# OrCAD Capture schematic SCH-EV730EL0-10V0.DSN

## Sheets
1 USB&POWER: size C; title: EV730EL0_USB&POWER; rev: 1.3; note: Ver1.0
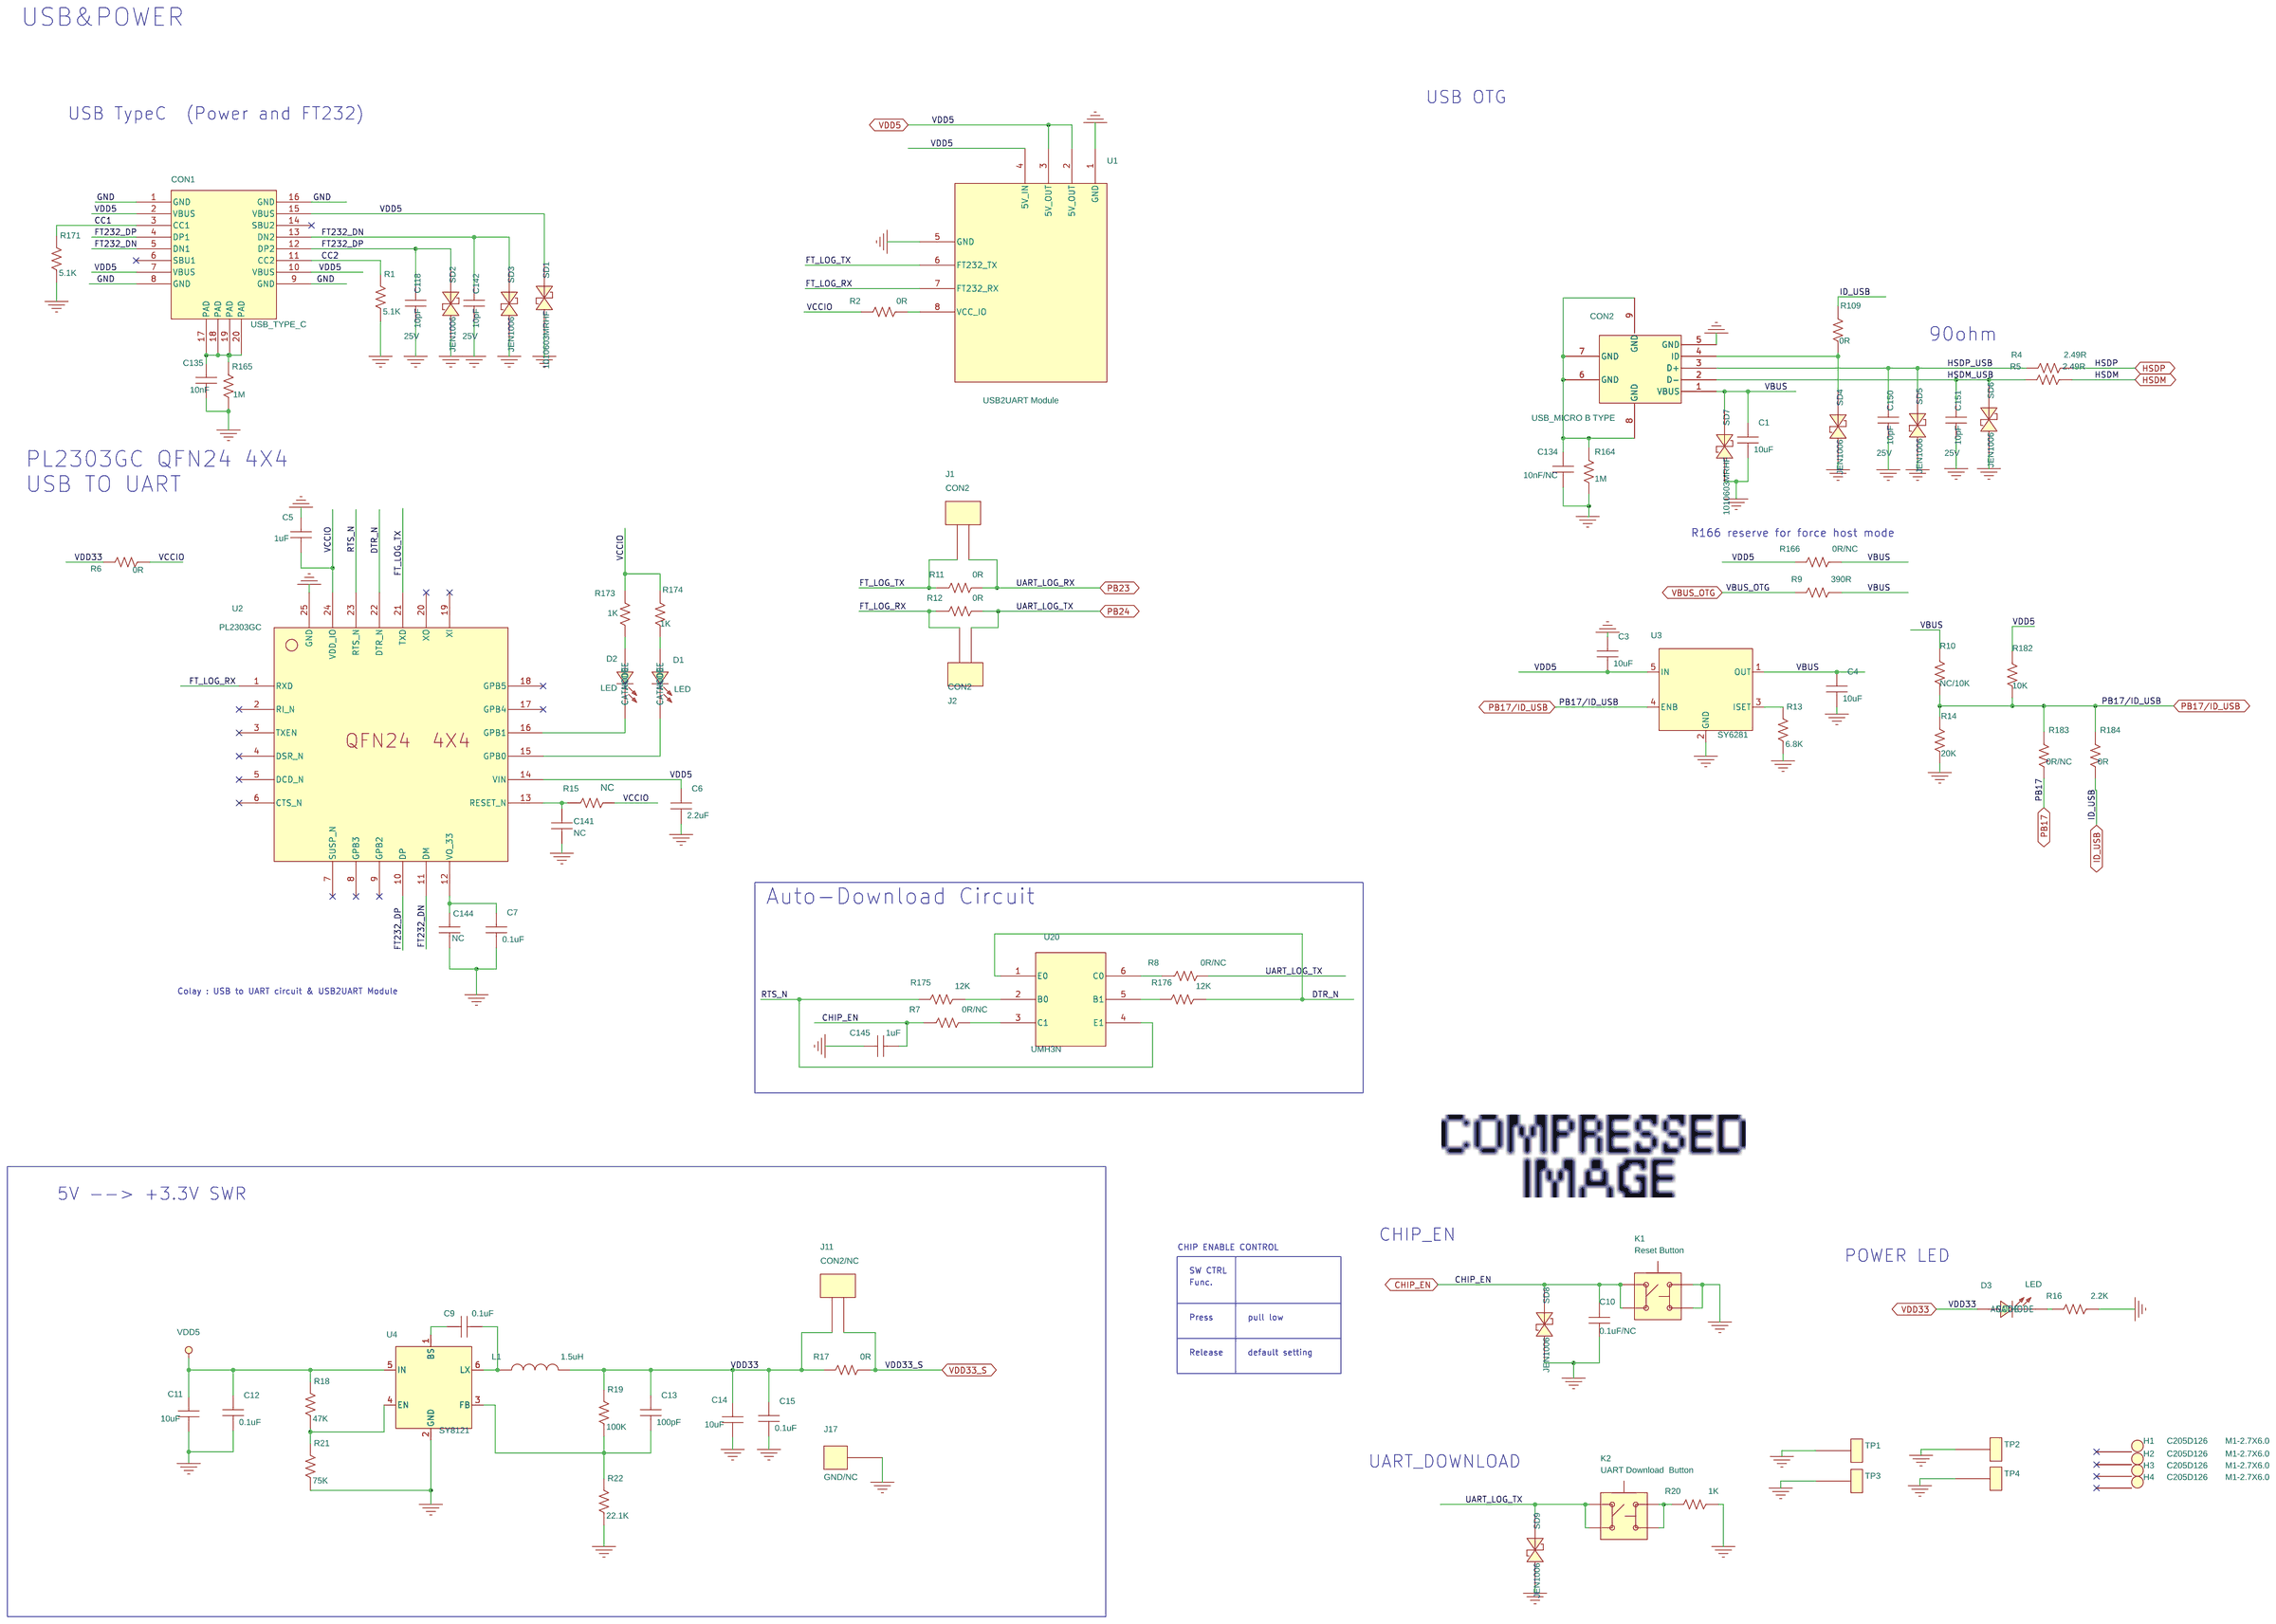
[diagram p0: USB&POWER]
2 8730EL_QFN144: size A2; title: EV730EL0
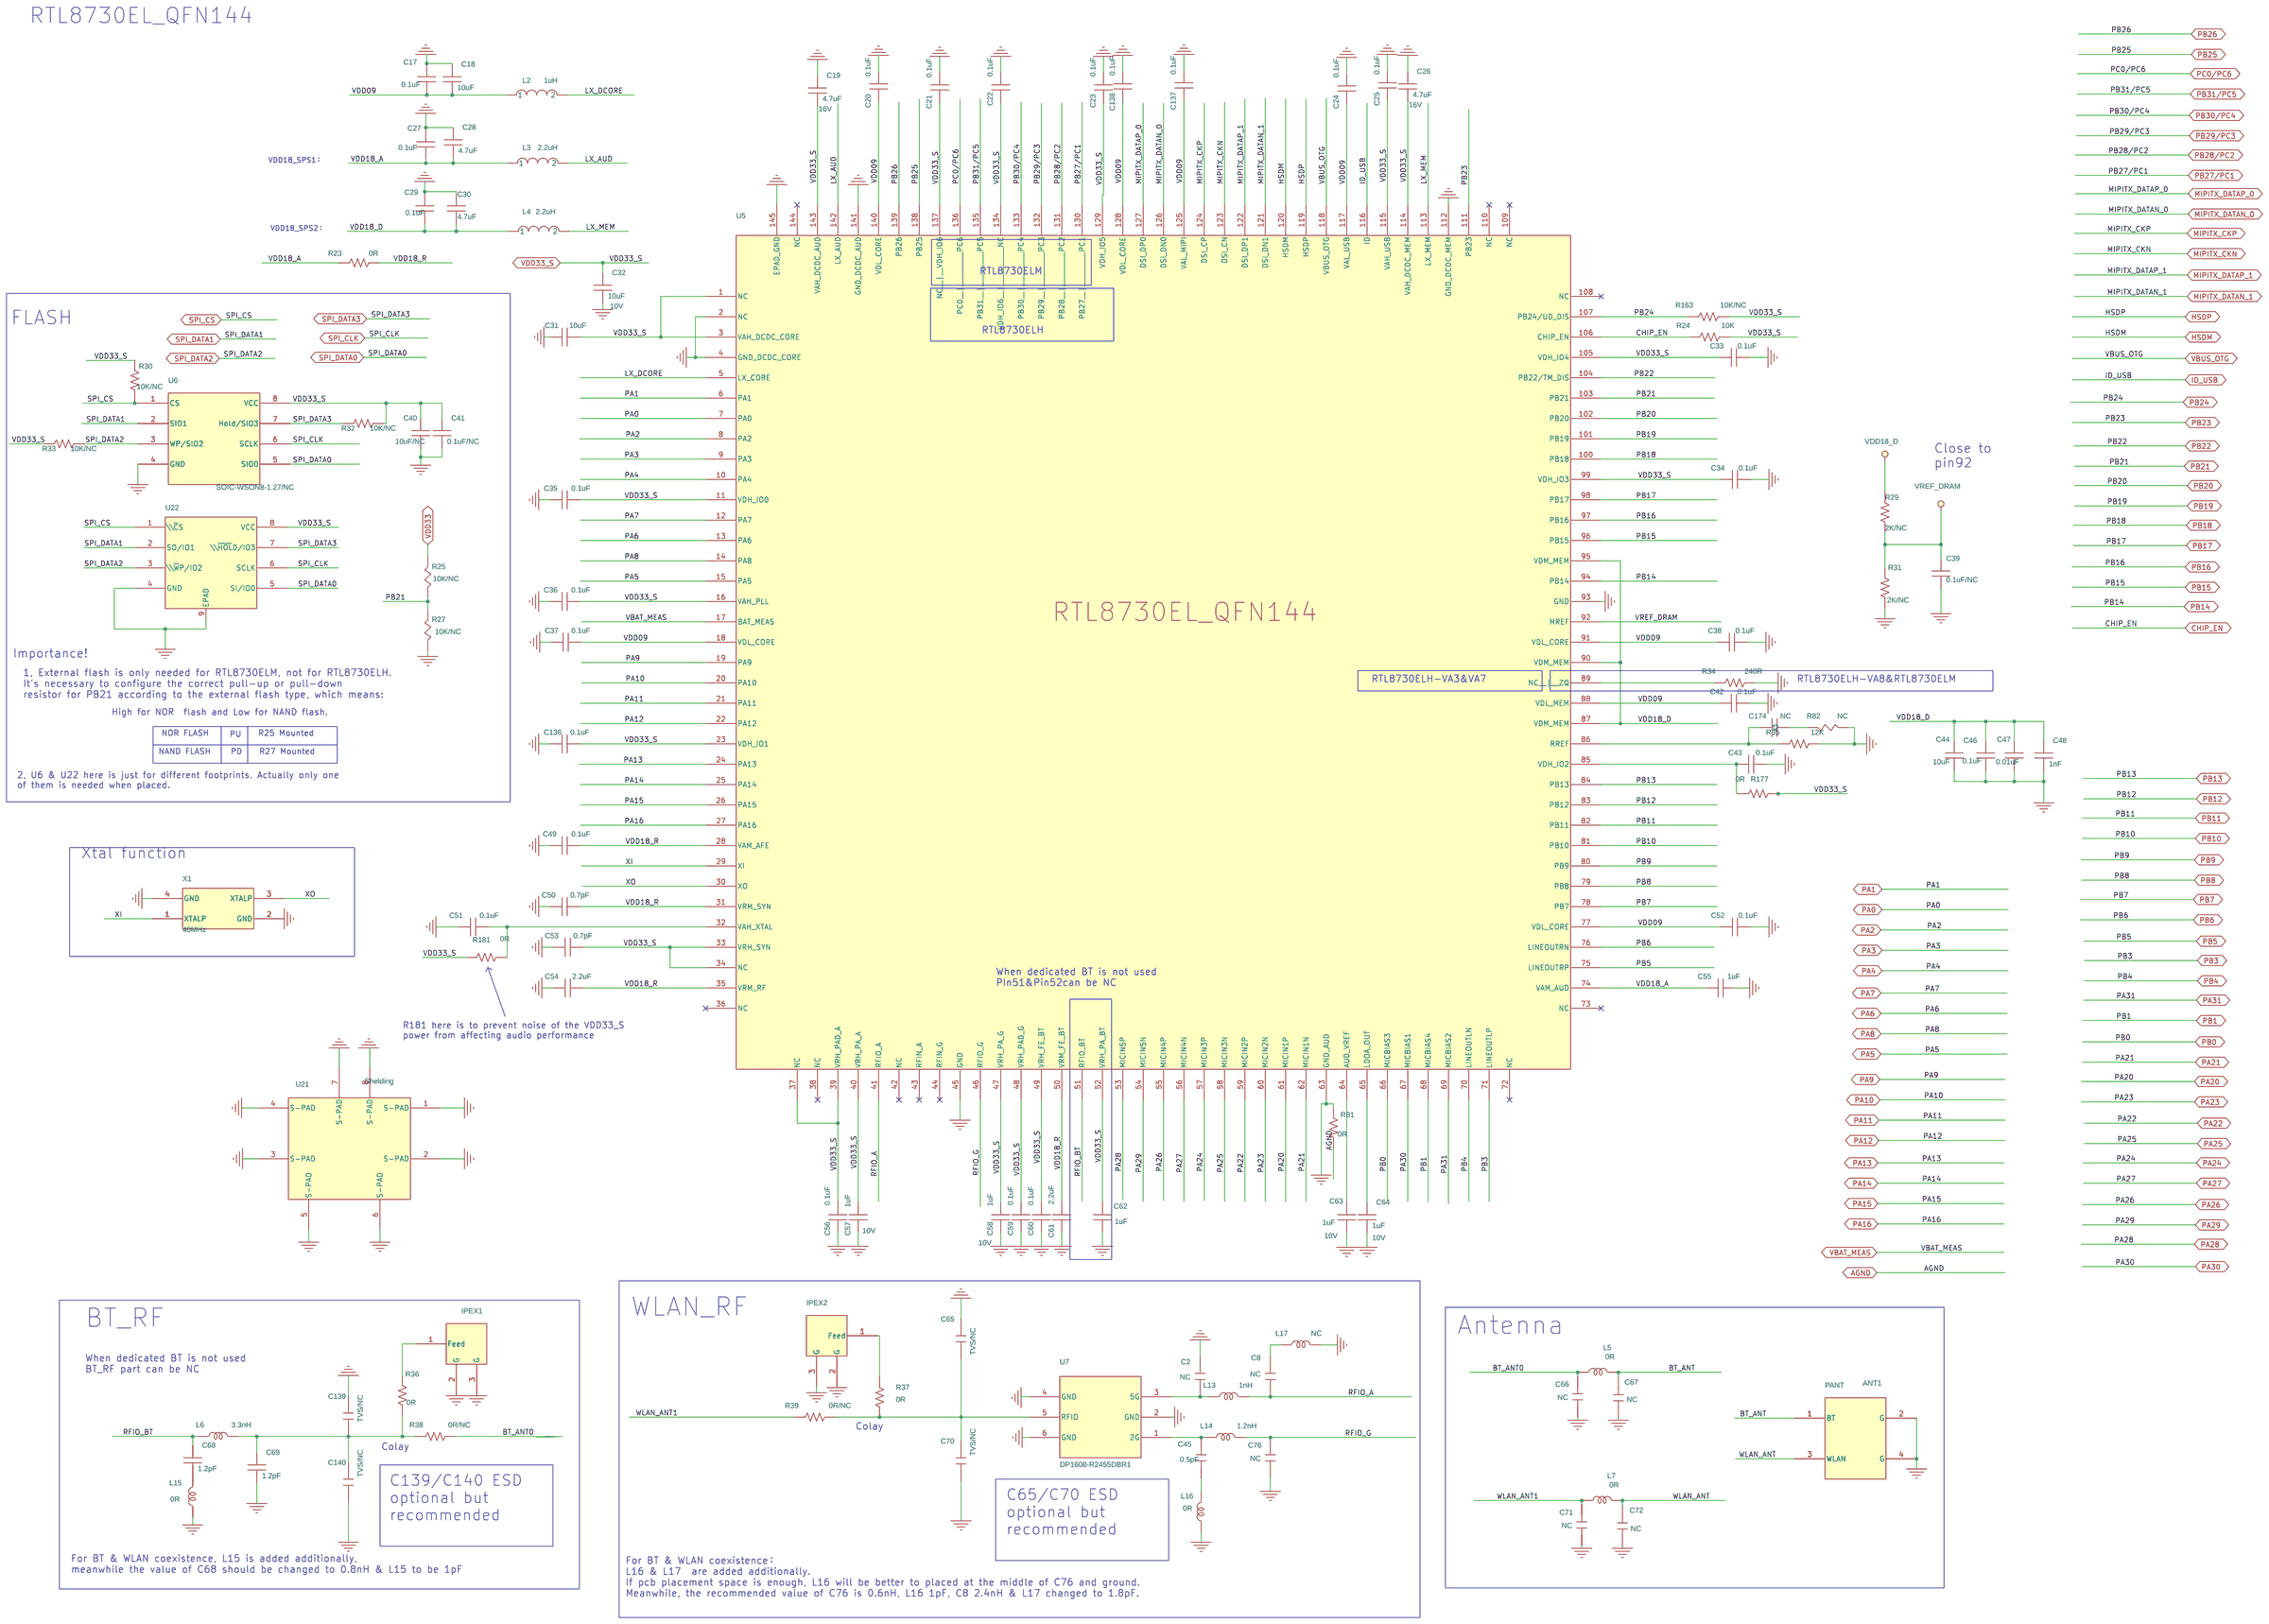
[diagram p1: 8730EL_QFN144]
3 AUDIO: size C; title: EV730EL0_AUDIO
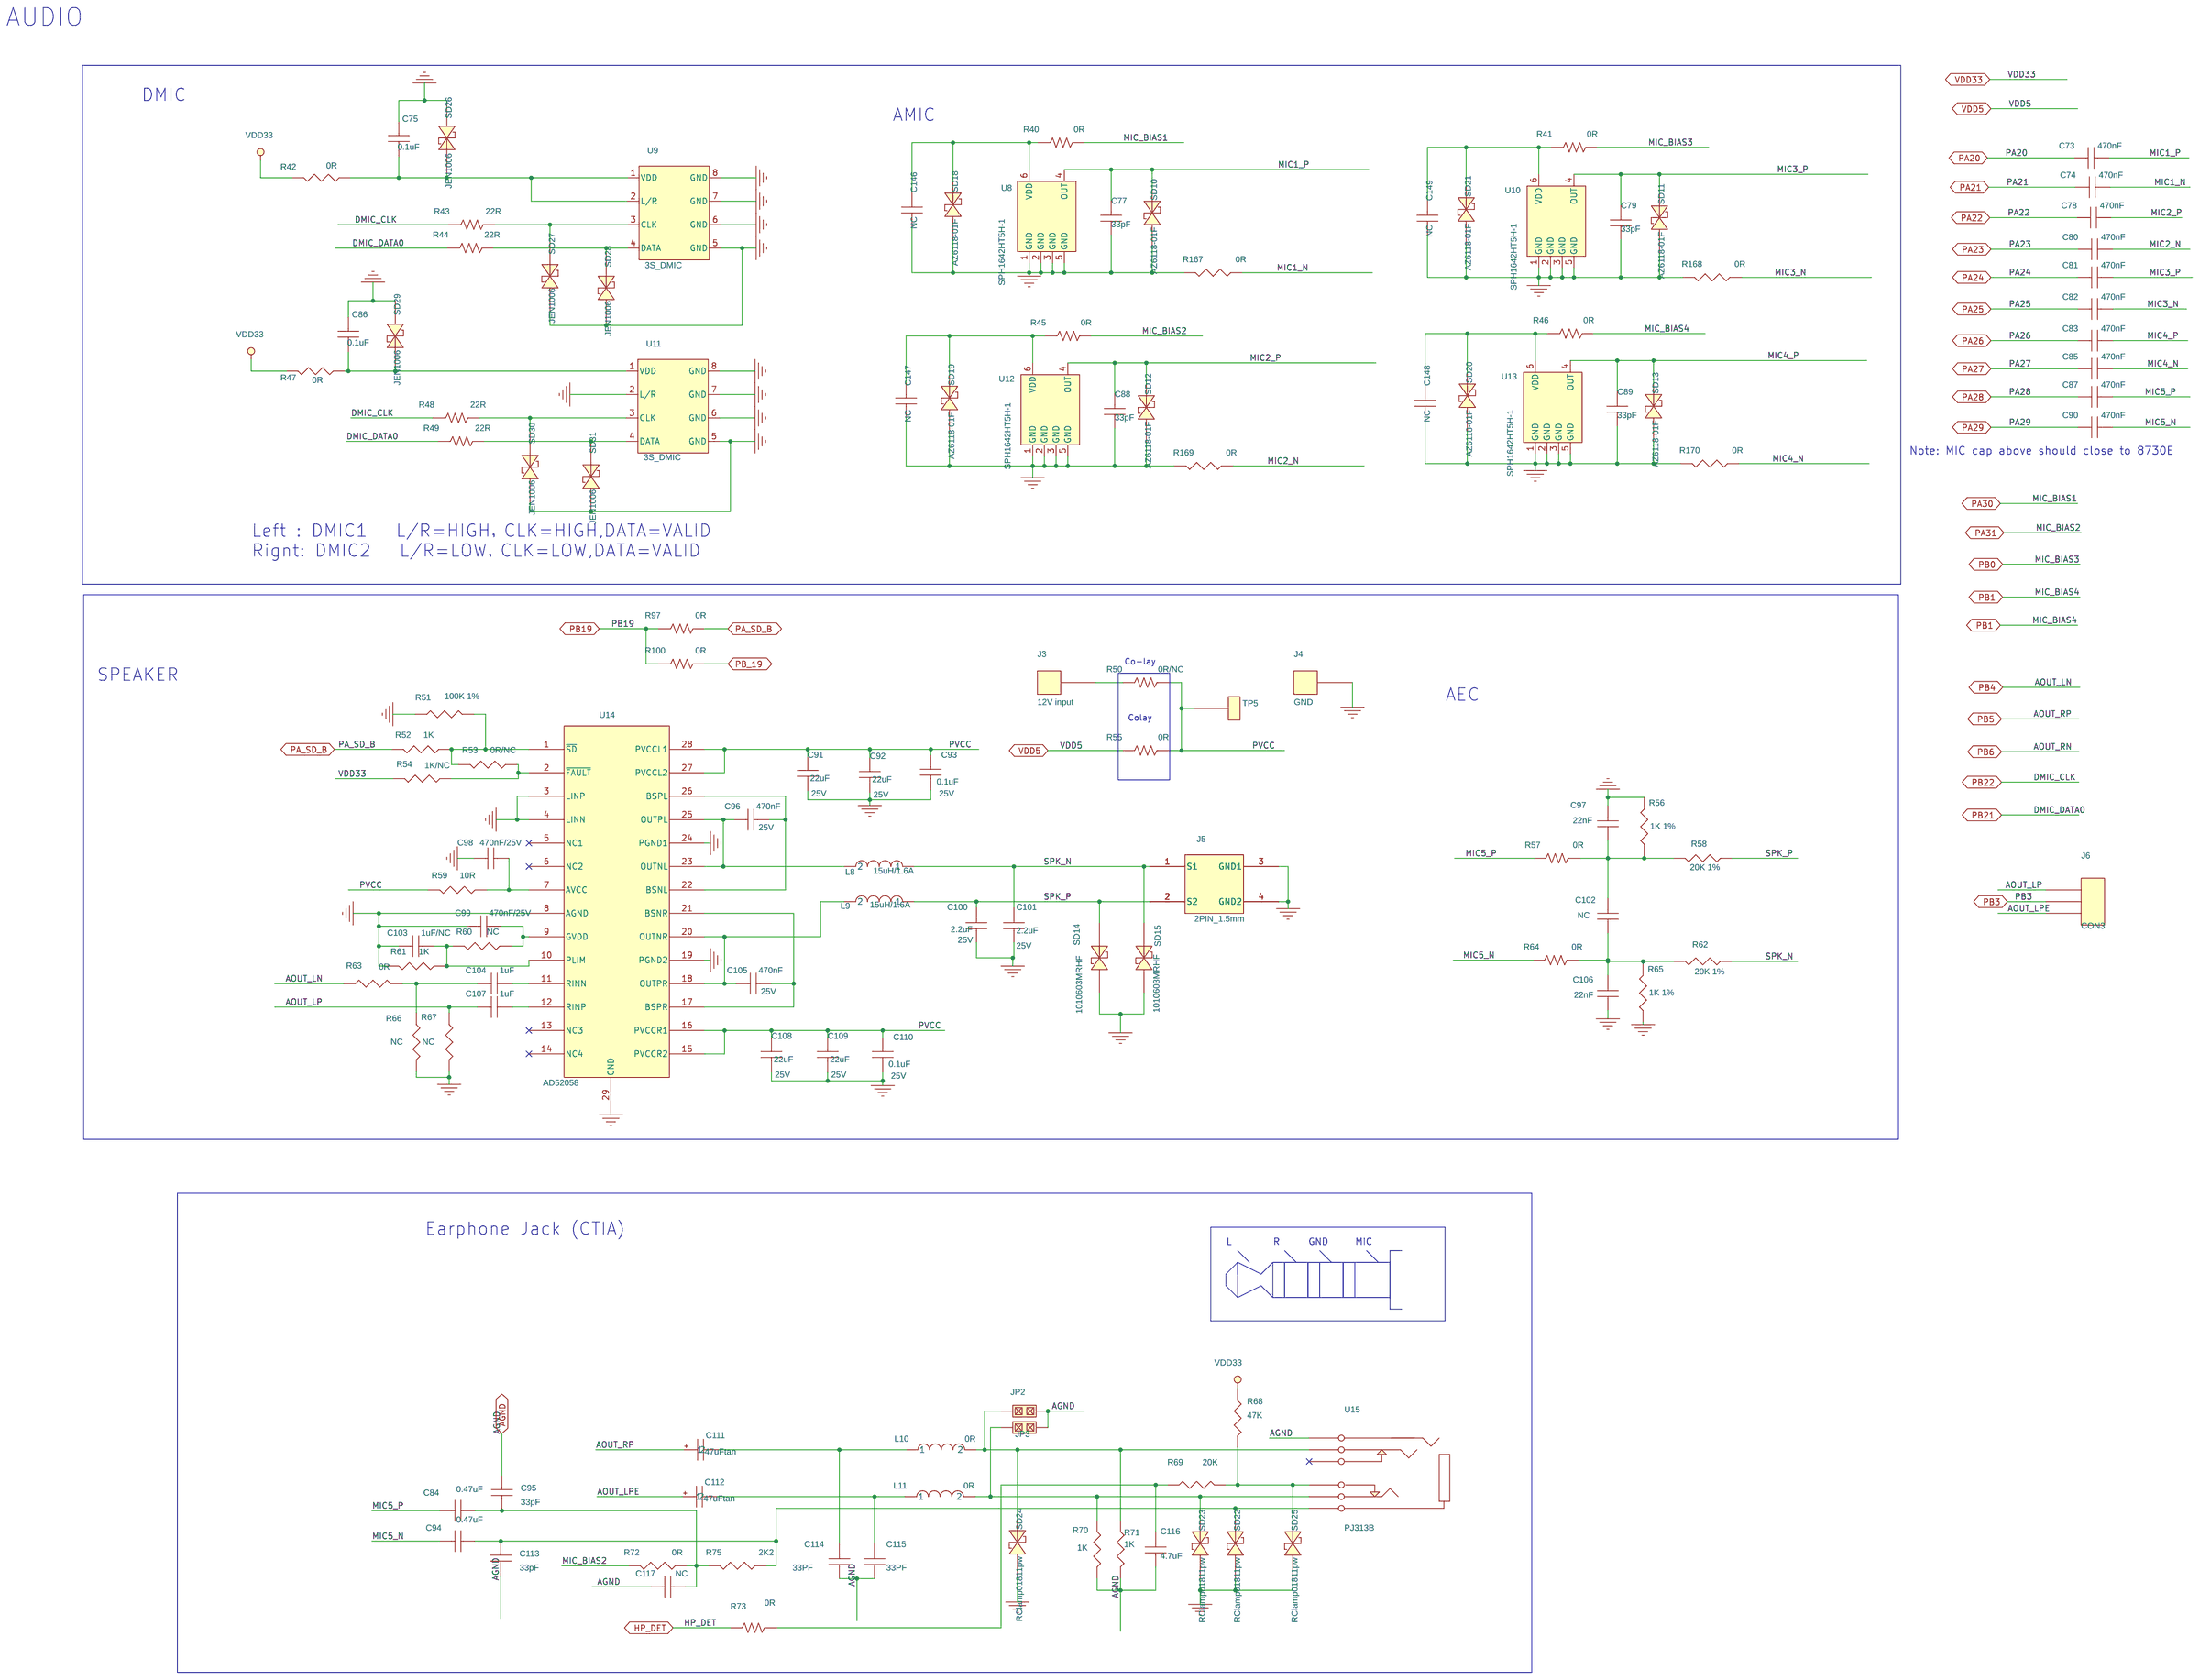
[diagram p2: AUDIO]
4 Peripheral: size C; title: EV730EL0_Peripheral
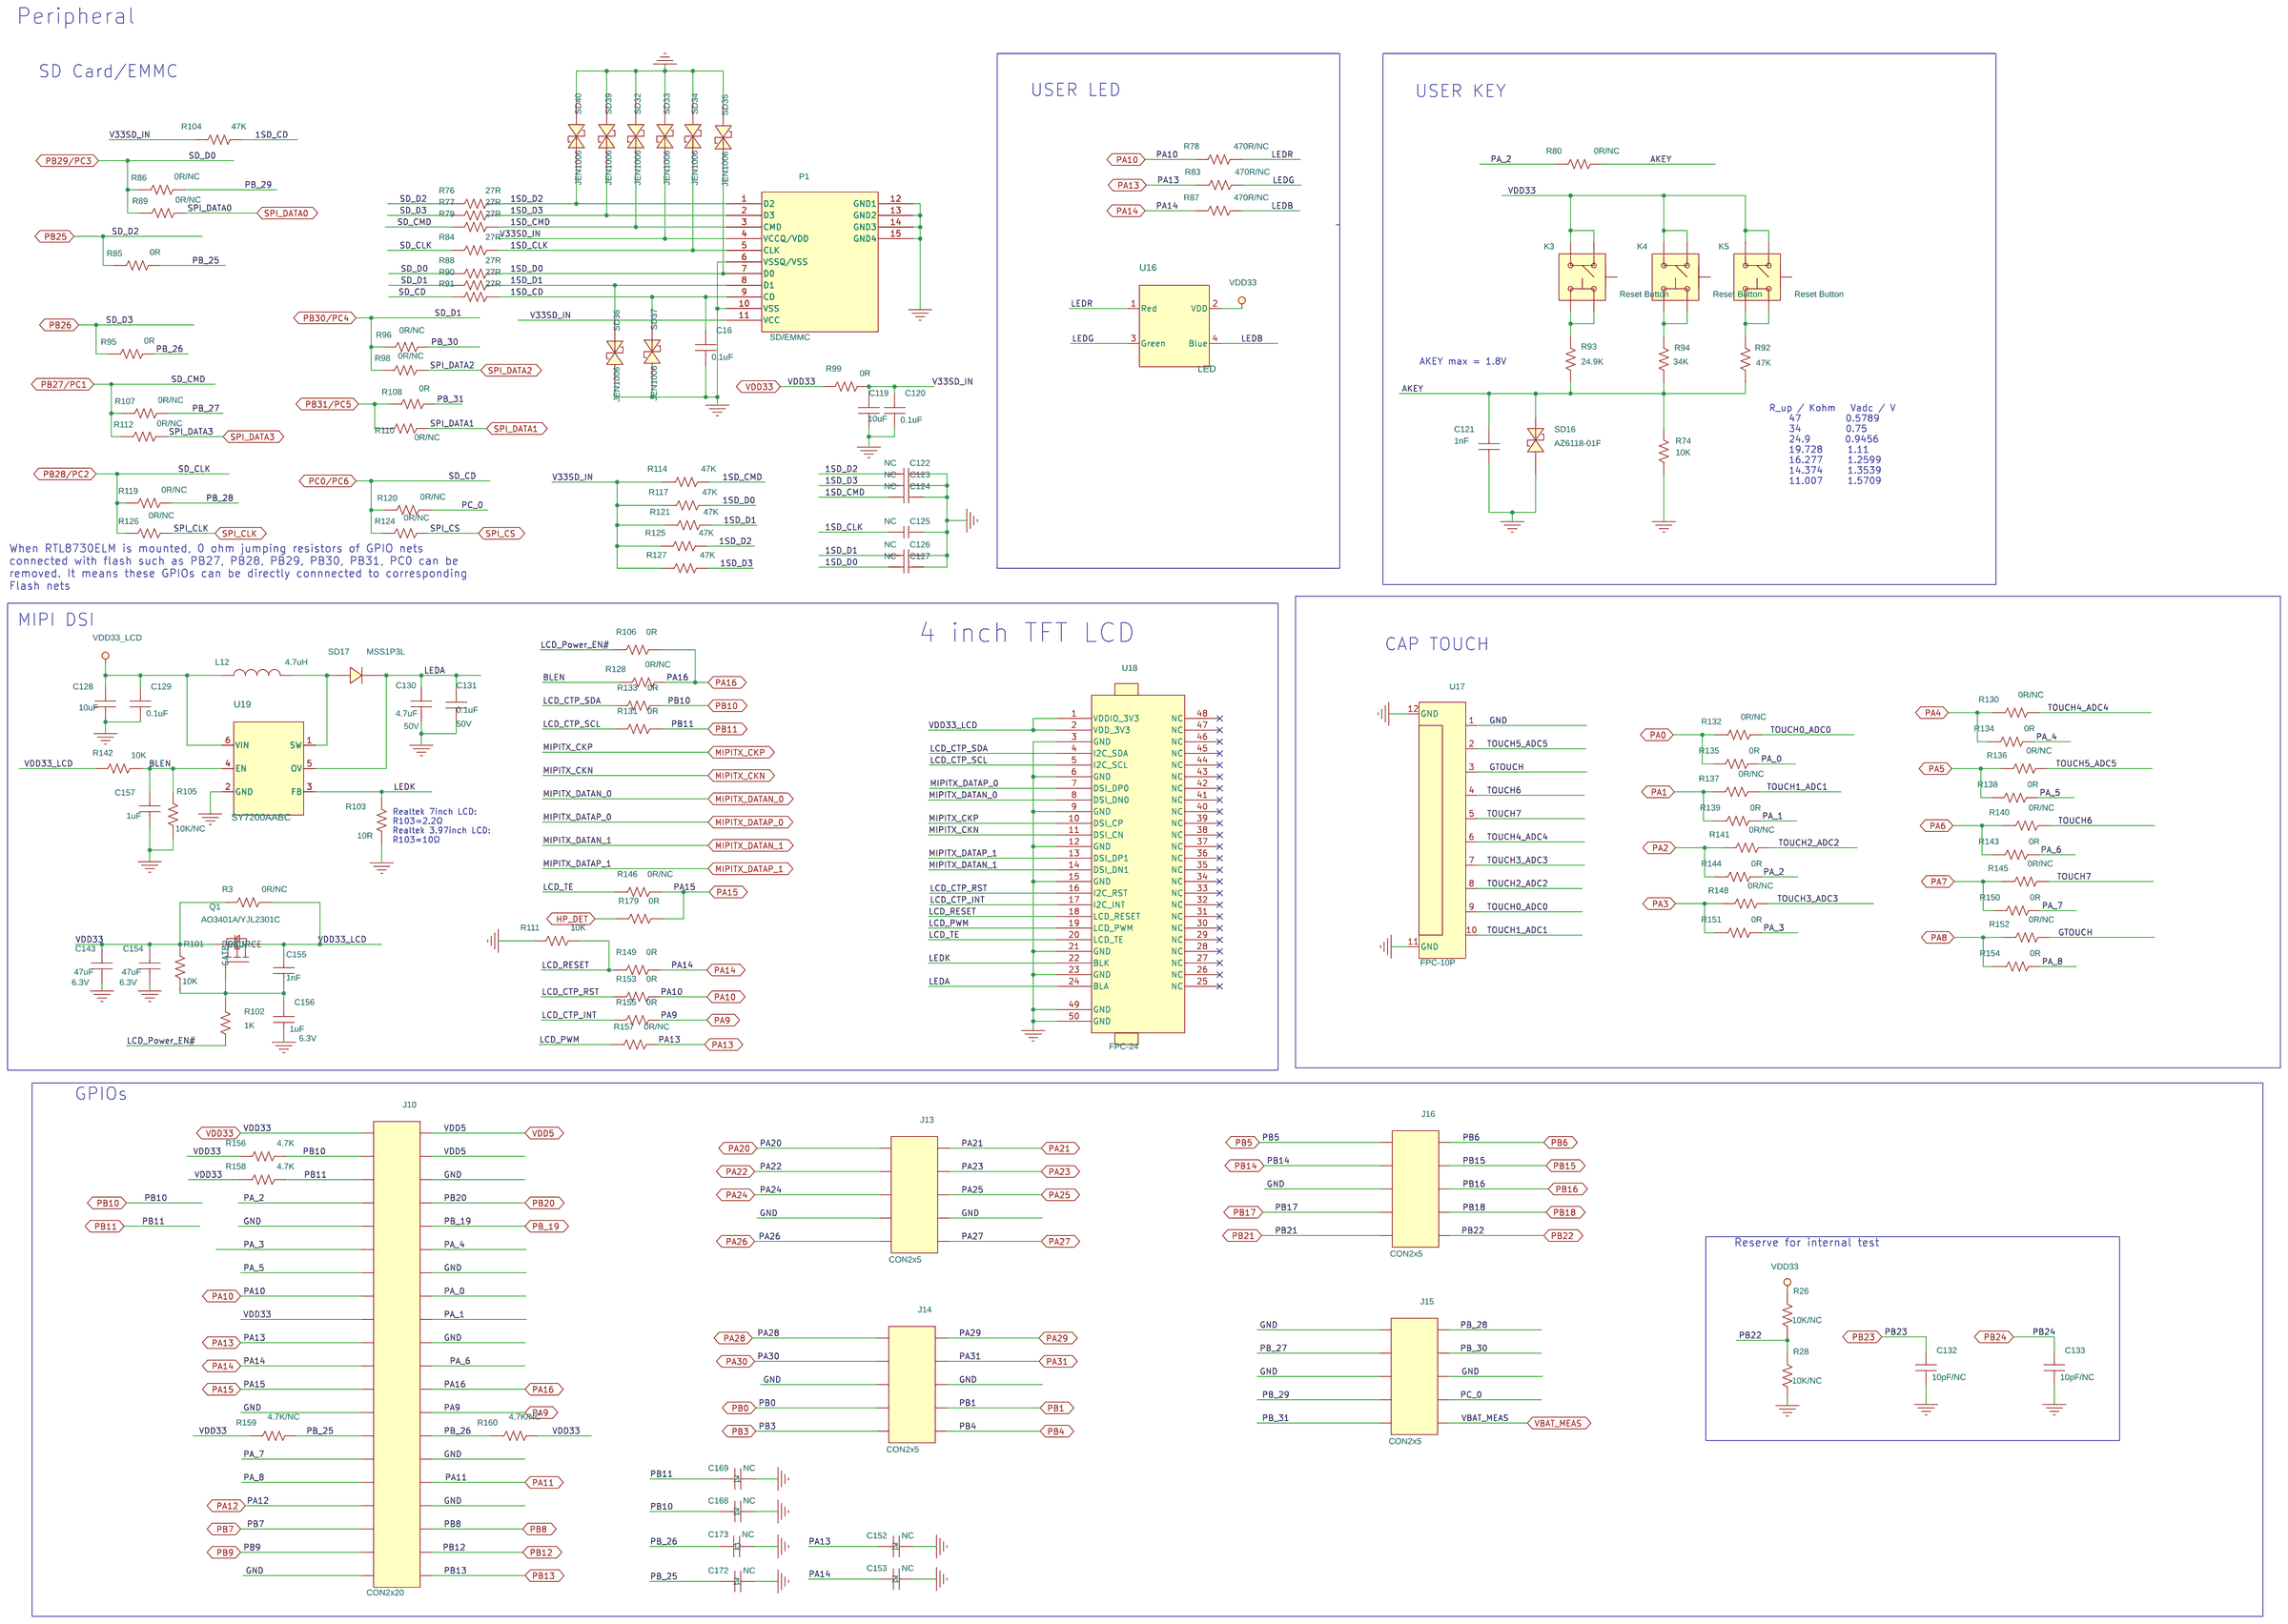
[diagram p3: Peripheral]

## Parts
sheet 8730EL_QFN144
ANT1  PANT  [8730EL_EVB_ANT]
C2  NC  [C0201]
C8  NC  [C0201]
C17  0.1uF  [C0201]
C18  10uF  [C0402]
C19  4.7uF  [C0402]
C20  0.1uF  [C0201]
C21  0.1uF  [C0201]
C22  0.1uF  [C0201]
C23  0.1uF  [C0201]
C24  0.1uF  [C0201]
C25  0.1uF  [C0201]
C26  4.7uF  [C0402]
C27  0.1uF  [C0201]
C28  4.7uF  [C0402]
C29  0.1uF  [C0201]
C30  4.7uF  [C0402]
C31  10uF  [C0402]
C32  10uF  [C0402]
C33  0.1uF  [C0201]
C34  0.1uF  [C0201]
C35  0.1uF  [C0201]
C36  0.1uF  [C0201]
C37  0.1uF  [C0201]
C38  0.1uF  [C0201]
C39  0.1uF/NC  [C0201]
C40  10uF/NC  [C0402]
C41  0.1uF/NC  [C0201]
C42  0.1uF  [C0201]
C43  0.1uF  [C0402]
C44  10uF  [C0402]
C45  0.5pF  [C0201]
C46  0.1uF  [C0201]
C47  0.01uF  [C0201]
C48  1nF  [C0201]
C49  0.1uF  [C0201]
C50  0.7pF  [C0201]
C51  0.1uF  [C0201]
C52  0.1uF  [C0201]
C53  0.7pF  [C0201]
C54  2.2uF  [C0201]
C55  1uF  [C0201]
C56  0.1uF  [C0201]
C57  1uF  [C0201]
C58  1uF  [C0201]
C59  0.1uF  [C0201]
C60  0.1uF  [C0201]
C61  2.2uF  [C0201]
C62  1uF  [C0201]
C63  1uF  [C0201]
C64  1uF  [C0201]
C65  TVS/NC  [C0201]
C66  NC  [C0201]
C67  NC  [C0201]
C68  1.2pF  [C0201]
C69  1.2pF  [C0201]
C70  TVS/NC  [C0402]
C71  NC  [C0201]
C72  NC  [C0201]
C76  NC  [C0201]
C136  0.1uF  [C0201]
C137  0.1uF  [C0201]
C138  0.1uF  [C0201]
C139  TVS/NC  [C0201]
C140  TVS/NC  [C0402]
C174  NC  [C0201]
IPEX1  TP  [IPEX-0.7X2.2-1.35]
IPEX2  TP  [IPEX-0.7X2.2-1.35]
L2  1uH  [L2016]
L3  2.2uH  [L2016]
L4  2.2uH  [L2016]
L5  0R  [L0201]
L6  3.3nH  [L0201]
L7  0R  [L0201]
L13  1nH  [L0201]
L14  1.2nH  [L0201]
L15  0R  [L0201]
L16  0R  [L0201]
L17  NC  [L0201]
R23  0R  [R0402]
R24  10K  [R0201]
R25  10K/NC  [R0201]
R27  10K/NC  [R0201]
R29  2K/NC  [R0201]
R30  10K/NC  [R0402]
R31  2K/NC  [R0201]
R32  10K/NC  [R0402]
R33  10K/NC  [R0402]
R34  240R  [R0201]
R35  12K  [R0201]
R36  0R  [R0201]
R37  0R  [R0201]
R38  0R/NC  [R0201]
R39  0R/NC  [R0201]
R81  0R  [R0201]
R82  NC  [R0201]
R163  10K/NC  [R0201]
R177  0R  [R0201]
R181  0R  [R0201]
U5  RL8730ELH  [QFN144-11X11_SMART]
U6  SOIC-WSON8-1.27/NC  [SOIC-WSON8-1.27]
U7  DP1608-R2455DBR1  [DPX1608-6-0.55-0.3X0.4]
U21  Shelding  [Shelding-144pin]
U22  Flash_2  [WSON8-1.27-8X6]
X1  40MHz  [XTAL-2016]
sheet AUDIO
C73  470nF  [C0201]
C74  470nF  [C0201]
C75  0.1uF  [C0402]
C77  33pF  [C0402]
C78  470nF  [C0201]
C79  33pF  [C0402]
C80  470nF  [C0201]
C81  470nF  [C0201]
C82  470nF  [C0201]
C83  470nF  [C0201]
C84  0.47uF  [C0402]
C85  470nF  [C0201]
C86  0.1uF  [C0402]
C87  470nF  [C0201]
C88  33pF  [C0402]
C89  33pF  [C0402]
C90  470nF  [C0201]
C91  22uF  [C0805]
C92  22uF  [C0805]
C93  0.1uF  [C0402]
C94  0.47uF  [C0402]
C95  33pF  [C0402]
C96  470nF  [C0402]
C97  22nF  [C0402]
C98  470nF/25V  [C0402]
C99  470nF/25V  [C0402]
C100  2.2uF  [C0402]
C101  2.2uF  [C0402]
C102  NC  [C0402]
C103  1uF/NC  [C0402]
C104  1uF  [C0402]
C105  470nF  [C0402]
C106  22nF  [C0402]
C107  1uF  [C0402]
C108  22uF  [C0805]
C109  22uF  [C0805]
C110  0.1uF  [C0402]
C111  47uFtan  [C0805-tan]
C112  47uFtan  [C0805-tan]
C113  33pF  [C0402]
C114  33PF  [C0402]
C115  33PF  [C0402]
C116  4.7uF  [C0402]
C117  NC  [C0402]
C146  NC  [C0402]
C147  NC  [C0402]
C148  NC  [C0402]
C149  NC  [C0402]
J3  12V input  [SIP-1P]
J4  GND  [SIP-1P]
J5  2PIN_1.5mm  [2PIN-1.5MM]
J6  CON3  [SIP3-2.54]
JP2  1X2PIN  [SIP2-2.54]
JP3  1X2PIN  [SIP2-2.54]
L8  15uH/1.6A  [L5050]
L9  15uH/1.6A  [L5050]
L10  0R  [L0603]
L11  0R  [L0603]
R40  0R  [R0402]
R41  0R  [R0402]
R42  0R  [R0402]
R43  22R  [R0402]
R44  22R  [R0402]
R45  0R  [R0402]
R46  0R  [R0402]
R47  0R  [R0402]
R48  22R  [R0402]
R49  22R  [R0402]
R50  0R/NC  [R0805]
R51  100K 1%  [R0402]
R52  1K  [R0402]
R53  0R/NC  [R0402]
R54  1K/NC  [R0402]
R55  0R  [R0805]
R56  1K 1%  [R0402]
R57  0R  [R0402]
R58  20K 1%  [R0402]
R59  10R  [R0402]
R60  NC  [R0402]
R61  1K  [R0402]
R62  20K 1%  [R0402]
R63  0R  [R0402]
R64  0R  [R0402]
R65  1K 1%  [R0402]
R66  NC  [R0402]
R67  NC  [R0402]
R68  47K  [R0402]
R69  20K  [R0402]
R70  1K  [R0402]
R71  1K  [R0402]
R72  0R  [R0402]
R73  0R  [R0402]
R75  2K2  [R0402]
R97  0R  [R0201]
R100  0R  [R0201]
R167  0R  [R0402]
R168  0R  [R0402]
R169  0R  [R0402]
R170  0R  [R0402]
SD10  AZ6118-01F  [D0402-AZ6118]
SD11  AZ6118-01F  [D0402-AZ6118]
SD12  AZ6118-01F  [D0402-AZ6118]
SD13  AZ6118-01F  [D0402-AZ6118]
SD14  1010603MRHF  [D0603-PGB]
SD15  1010603MRHF  [D0603-PGB]
SD18  AZ6118-01F  [D0402-AZ6118]
SD19  AZ6118-01F  [D0402-AZ6118]
SD20  AZ6118-01F  [D0402-AZ6118]
SD21  AZ6118-01F  [D0402-AZ6118]
SD22  RClamp01811pw  [D0402-AZ6118]
SD23  RClamp01811pw  [D0402-AZ6118]
SD24  RClamp01811pw  [D0402-AZ6118]
SD25  RClamp01811pw  [D0402-AZ6118]
SD26  JEN1006  [D0402-JEN]
SD27  JEN1006  [D0402-JEN]
SD28  JEN1006  [D0402-JEN]
SD29  JEN1006  [D0402-JEN]
SD30  JEN1006  [D0402-JEN]
SD31  JEN1006  [D0402-JEN]
TP5  TEST POINT  [TP]
U8  SPH1642HT5H-1  [LGA]
U9  3S_DMIC  [LGA8-4X3]
U10  SPH1642HT5H-1  [LGA]
U11  3S_DMIC  [LGA8-4X3]
U12  SPH1642HT5H-1  [LGA]
U13  SPH1642HT5H-1  [LGA]
U14  AD52058  [E-TSSOP-28L]
U15  PJ313B  [AUDIO_JACK]
sheet Peripheral
C16  0.1uF  [C0402]
C119  10uF  [C0402]
C120  0.1uF  [C0402]
C121  1nF  [C0402]
C122  NC  [C0402]
C123  NC  [C0402]
C124  NC  [C0402]
C125  NC  [C0402]
C126  NC  [C0402]
C127  NC  [C0402]
C128  10uF  [C0402]
C129  0.1uF  [C0201]
C130  4.7uF  [C0805]
C131  0.1uF  [C0603]
C132  10pF/NC  [C0402]
C133  10pF/NC  [C0402]
C143  47uF  [C0603]
C152  NC  [C0402]
C153  NC  [C0402]
C154  47uF  [C0603]
C155  1nF  [C0402]
C156  1uF  [C0402]
C157  1uF  [C0402]
C168  NC  [C0402]
C169  NC  [C0402]
C172  NC  [C0402]
C173  NC  [C0402]
J10  CON2x20  [SIP20X2-2.54]
J13  CON2x5  [SIP5X2-2.54]
J14  CON2x5  [SIP5X2-2.54]
J15  CON2x5  [SIP5X2-2.54]
J16  CON2x5  [SIP5X2-2.54]
K3  Reset Button  [SW-4P-3X4]
K4  Reset Button  [SW-4P-3X4]
K5  Reset Button  [SW-4P-3X4]
L12  4.7uH  [L4442]
P1  SD/EMMC  [SD_MODULE_QA]
Q1  AO3401A/YJL2301C  [SOT-23]
R3  0R/NC  [R0603]
R26  10K/NC  [R0201]
R28  10K/NC  [R0201]
R74  10K  [R0402]
R76  27R  [R0201]
R77  27R  [R0201]
R78  470R/NC  [R0402]
R79  27R  [R0201]
R80  0R/NC  [R0402]
R83  470R/NC  [R0402]
R84  27R  [R0201]
R85  0R  [R0201]
R86  0R/NC  [R0201]
R87  470R/NC  [R0402]
R88  27R  [R0201]
R89  0R/NC  [R0201]
R90  27R  [R0201]
R91  27R  [R0201]
R92  47K  [R0402]
R93  24.9K  [R0402]
R94  34K  [R0402]
R95  0R  [R0201]
R96  0R/NC  [R0201]
R98  0R/NC  [R0201]
R99  0R  [R0402]
R101  10K  [R0402]
R102  1K  [R0402]
R103  10R  [R0402]
R104  47K  [R0402]
R105  10K/NC  [R0402]
R106  0R  [R0402]
R107  0R/NC  [R0201]
R108  0R  [R0201]
R110  0R/NC  [R0201]
R111  10K  [R0402]
R112  0R/NC  [R0201]
R114  47K  [R0402]
R117  47K  [R0402]
R119  0R/NC  [R0201]
R120  0R/NC  [R0201]
R121  47K  [R0402]
R124  0R/NC  [R0201]
R125  47K  [R0402]
R126  0R/NC  [R0201]
R127  47K  [R0402]
R128  0R/NC  [R0402]
R130  0R/NC  [R0402]
R131  0R  [R0402]
R132  0R/NC  [R0402]
R133  0R  [R0402]
R134  0R  [R0402]
R135  0R  [R0402]
R136  0R/NC  [R0402]
R137  0R/NC  [R0402]
R138  0R  [R0402]
R139  0R  [R0402]
R140  0R/NC  [R0402]
R141  0R/NC  [R0402]
R142  10K  [R0402]
R143  0R  [R0402]
R144  0R  [R0402]
R145  0R/NC  [R0402]
R146  0R/NC  [R0402]
R148  0R/NC  [R0402]
R149  0R  [R0402]
R150  0R  [R0402]
R151  0R  [R0402]
R152  0R/NC  [R0402]
R153  0R  [R0402]
R154  0R  [R0402]
R155  0R  [R0402]
R156  4.7K  [R0402]
R157  0R/NC  [R0402]
R158  4.7K  [R0402]
R159  4.7K/NC  [R0402]
R160  4.7K/NC  [R0402]
R179  0R  [R0402]
SD16  AZ6118-01F  [D0402-AZ6118]
SD17  MSS1P3L  [DO-219AD]
SD32  JEN1006  [D0402-JEN]
SD33  JEN1006  [D0402-JEN]
SD34  JEN1006  [D0402-JEN]
SD35  JEN1006  [D0402-JEN]
SD36  JEN1006  [D0402-JEN]
SD37  JEN1006  [D0402-JEN]
SD39  JEN1006  [D0402-JEN]
SD40  JEN1006  [D0402-JEN]
U16  LED  [LED3-3.5X2.8]
U17  FPC-10P  [FPC-10-1mm]
U18  FPC-24  [FPC-MIPI-24P-15P]
U19  SY7200AABC  [SOT-23-6]
sheet USB&POWER
C1  10uF  [C0402]
C3  10uF  [C0402]
C4  10uF  [C0402]
C5  1uF  [C0402]
C6  2.2uF  [C0402]
C7  0.1uF  [C0402]
C9  0.1uF  [C0402]
C10  0.1uF/NC  [C0402]
C11  10uF  [C0402]
C12  0.1uF  [C0402]
C13  100pF  [C0402]
C14  10uF  [C0402]
C15  0.1uF  [C0402]
C118  10pF  [C0201]
C134  10nF/NC  [C0402]
C135  10nF  [C0402]
C141  NC  [C0402]
C142  10pF  [C0201]
C144  NC  [C0402]
C145  1uF  [C0603]
C150  10pF  [C0201]
C151  10pF  [C0201]
CON1  USB_TYPE_C  [USB-C-SMT]
CON2  USB_MICRO B TYPE  [USB-MICRO-B-SMT-3]
D1  LED  [LED-0603]
D2  LED  [LED-0603]
D3  LED  [LED-0805]
H1  C205D126  [M1-2.7X6.0]
H2  C205D126  [M1-2.7X6.0]
H3  C205D126  [M1-2.7X6.0]
H4  C205D126  [M1-2.7X6.0]
J1  CON2  [SIP2-2.54]
J2  CON2  [SIP2-2.54]
J11  CON2/NC  [SIP2-2.54]
J17  GND/NC  [SIP-1P]
K1  Reset Button  [SW-4P-3X4]
K2  UART Download  Button  [SW-4P-3X4]
L1  1.5uH  [L4442]
R1  5.1K  [R0402]
R2  0R  [R0402]
R4  2.49R  [R0402]
R5  2.49R  [R0402]
R6  0R  [R0402]
R7  0R/NC  [R0402]
R8  0R/NC  [R0402]
R9  390R  [R0402]
R10  NC/10K  [R0402]
R11  0R  [R0402]
R12  0R  [R0402]
R13  6.8K  [R0402]
R14  20K  [R0402]
R15  NC  [R0402]
R16  2.2K  [R0402]
R17  0R  [R0805]
R18  47K  [R0402]
R19  100K  [R0402]
R20  1K  [R0402]
R21  75K  [R0402]
R22  22.1K  [R0402]
R109  0R  [R0402]
R164  1M  [R0402]
R165  1M  [R0402]
R166  0R/NC  [R0603]
R171  5.1K  [R0402]
R173  1K  [R0402]
R174  1K  [R0402]
R175  12K  [R0402]
R176  12K  [R0402]
R182  10K  [R0402]
R183  0R/NC  [R0402]
R184  0R  [R0402]
SD1  1010603MRHF  [D0603-PGB]
SD2  JEN1006  [D0402-JEN]
SD3  JEN1006  [D0402-JEN]
SD4  JEN1006  [D0402-JEN]
SD5  JEN1006  [D0402-JEN]
SD6  JEN1006  [D0402-JEN]
SD7  1010603MRHF  [D0603-PGB]
SD8  JEN1006  [D0402-JEN]
SD9  JEN1006  [D0402-JEN]
TP1  TEST POINT  [TP]
TP2  TEST POINT  [TP]
TP3  TEST POINT  [TP]
TP4  TEST POINT  [TP]
U1  USB2UART Module  [MODULE_USB_FT232_2]
U2  PL2303GC  [UQFN24-4X4-PL2303GC]
U3  SY6281  [SOT-23-5]
U4  SY8121  [SOT-23-6]
U20  UMH3N  [SOT-363]

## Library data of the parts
ANT1 = TP_1
C2 C8 C45 C65-C67 C70-C72 C76 C139 C140 = C_402
C17 C27 C29 = CAPACITOR_NON-POL_0: ±10%,16V,X7R; Manufacturer: MURATA; Part Number: GRM033Z71C104KE14D; Voltage: 16V
C1 C3 C4 C11 C14 C18 C31 C32 C40 C44 C119 C128 = CAPACITOR_NON-POL_0: ±20%,10V,X5R; Manufacturer: WALSIN; Part Number: 0402X106M100CT; Voltage: 10V; Datasheet: \\172.29.17.1\cn\WLAN\WLAN2\boarddesignLIB\53_component_database\Datasheet\Capacitor\Capacitor_Walsin_MLCC.pdf
C19 C26 C28 C30 = CAPACITOR_NON-POL_0: ±20%,16V,X5R; Manufacturer: WALSIN; Part Number: 0402X475M160CT; Voltage: 16V; Datasheet: \\172.29.17.1\cn\WLAN\WLAN2\boarddesignLIB\147_component_database\Datasheet\Capacitor\Capacitor_Walsin_MLCC.pdf
C20-C25 C33-C39 C41 C42 C46 C49 C51 C52 C56 C59 C60 C129 C136-C138 = CAPACITOR_NON-POL_0: ±10%,10V,X5R; Manufacturer: WALSIN; Part Number: 0201X104K100CT; Voltage: 10V; Datasheet: \\172.29.17.1\cn\WLAN\WLAN2\boarddesignLIB\04_component_database\Datasheet\Capacitor\Capacitor_Walsin_MLCC.pdf
C7 C9 C10 C12 C15 C16 C43 C75 C86 C93 C110 C120 = CAPACITOR_NON-POL_0: ±10%,25V,X7R; Manufacturer: WALSIN; Part Number: 0402B104K250CT; Voltage: 25V; Datasheet: \\172.29.17.1\cn\WLAN\WLAN2\boarddesignLIB\06_component_database\Datasheet\Capacitor\Capacitor_Walsin_MLCC.pdf
C47 = CAPACITOR_NON-POL_0: ±10%,6.3V,X5R; Manufacturer: WALSIN; Part Number: 0201X103K6R3CT; Voltage: 6.3V; Datasheet: \\172.29.17.1\cn\WLAN\WLAN2\boarddesignLIB\02_component_database\Datasheet\Capacitor\Capacitor_Walsin_MLCC.pdf
C48 = CAPACITOR_NON-POL_0: 10%,16V,X7R; Manufacturer: WALSIN; Part Number: 0201B102K160CT; Voltage: 16V; Datasheet: \\172.29.17.1\cn\WLAN\WLAN2\boarddesignLIB\77_component_database\Datasheet\Capacitor\Capacitor_Walsin_MLCC.pdf
C50 C53 = CAPACITOR_NON-POL_0: ±0.1pF,25V,NPO,Y; Manufacturer: WALSIN; Part Number: RF03N0R7B250CT; Voltage: 25V; Datasheet: \\172.29.17.1\cn\WLAN\WLAN2\boarddesignLIB\22_component_database\Datasheet\Capacitor\Capacitor_Walsin_MLCC.pdf
C54 C61 = CAPACITOR_NON-POL_0: ±20%,6.3V,X5R; Manufacturer: WALSIN; Part Number: 0201X225M6R3CT; Voltage: 6.3V; Datasheet: \\172.29.17.1\cn\WLAN\WLAN2\boarddesignLIB\92_component_database\Datasheet\Capacitor\Capacitor_Walsin_MLCC.pdf
C55 C57 C58 C62-C64 = CAPACITOR_NON-POL_0: ±20%,10V,X5R; Manufacturer: WALSIN; Part Number: 0201X105M100CT; Voltage: 10V; Datasheet: \\172.29.17.1\cn\WLAN\WLAN2\boarddesignLIB\82_component_database\Datasheet\Capacitor\Capacitor_Walsin_MLCC.pdf
C68 C69 = CAPACITOR_NON-POL_0: +/-0.1pF,25V,NPO,Y; Manufacturer: WALSIN; Part Number: RF03N1R2B250CT; Voltage: 25V; Datasheet: \\172.29.17.1\cn\WLAN\WLAN2\boarddesignLIB\31_component_database\Datasheet\Capacitor\Capacitor_Walsin_MLCC.pdf
C153 C174 = C_v2: X5R, ∮20%, 6.3V; Manufacturer: WALSIN; Part Number: 0805X106K6R3CT; Unit Price(USD): 0.01048
IPEX1 IPEX2 = TP_3
L2 L11 = INDUCTOR
L3 L10 = INDUCTOR_2
L4 L9 = INDUCTOR_1
L5 L7 L13-L17 = L0402_1.7NH_ACX
L6 = Inductor_RF: ±0.3nH,5min; Manufacturer: TAIYO YUDEN; Part Number: HK06033N3S-T
R2 R6-R8 R11 R12 R23 R40 R41 R45 R46 R57 R64 R73 R80 R99 R106 R109 R128 R130-R141 R143-R146 R148-R155 R157 R179 R183 R184 = RES_0: JUMPER; Manufacturer: WALSIN; Part Number: WR04X000PTL; Datasheet: \\172.29.17.1\cn\WLAN\WLAN2\boarddesignLIB\01_component_database\Datasheet\Resistor\Resistor_Walsin_chipR.pdf
R24 R26 R28 R163 = RES_0: +/-1%; Manufacturer: WALSIN; Part Number: WR02X1002FAL; Datasheet: \\172.29.17.1\cn\WLAN\WLAN2\boarddesignLIB\01_component_database\Datasheet\Resistor\Resistor_Walsin_chipR.pdf
R25 R27 R82 = R0402_1.06K_WALSIN
R29 R31 = RES_0: +/-1%; Manufacturer: WALSIN; Part Number: WR02X2001FAL; Datasheet: \\172.29.17.1\cn\WLAN\WLAN2\boarddesignLIB\01_component_database\Datasheet\Resistor\Resistor_Walsin_chipR.pdf
R10 R30 R32 R33 R101 R105 R111 R142 R182 = RES_0: +/-1%; Manufacturer: WALSIN; Part Number: WR04X1002 FTL; Datasheet: \\172.29.17.1\cn\WLAN\WLAN2\boarddesignLIB\01_component_database\Datasheet\Resistor\Resistor_Walsin_chipR.pdf
R34 = RES_0: +/-1%; Manufacturer: WALSIN; Part Number: WR02X2400FAL; Datasheet: \\172.29.17.1\cn\WLAN\WLAN2\boarddesignLIB\01_component_database\Datasheet\Resistor\Resistor_Walsin_chipR.pdf
R35 = RES_0: +/-1%; Manufacturer: WALSIN; Part Number: WR02X1202FAL; Datasheet: \\172.29.17.1\cn\WLAN\WLAN2\boarddesignLIB\01_component_database\Datasheet\Resistor\Resistor_Walsin_chipR.pdf
R36-R39 R85 R86 R89 R95-R98 R100 R107 R108 R110 R112 R119 R120 R124 R126 = RES_0: JUMPER; Manufacturer: WALSIN; Part Number: WR02X000PTL; Datasheet: \\172.29.17.1\cn\WLAN\WLAN2\boarddesignLIB\01_component_database\Datasheet\Resistor\Resistor_Walsin_chipR.pdf
R81 R94 = R_v3_2
R93 R177 = R_v3_1
R74 R181 = R_v3
U5 = RL5760_75
U6 = 9346_1
U7 = DPX_1: Manufacturer: ACX; Datasheet: \\172.29.17.1\cn\WLAN\WLAN2\boarddesignLIB\01_component_database\Datasheet\RF Chip\DPX_ACX_DP1608-R2455DBR1_Preliminary_S-R00-N1823_1.pdf
U21 = Shelding_3
U22 = Flash_2: 1 E-Pad; Part Number: FLASH
X1 = 9346_0
C73 C74 C78 C80-C83 C85 C87 C90 = CAPACITOR_NON-POL_0: ±10%,6.3V,X5R; Manufacturer: WALSIN; Part Number: 0201X474K6R3CT; Voltage: 6.3V; Datasheet: \\172.29.17.1\cn\WLAN\WLAN2\boarddesignLIB\154_component_database\Datasheet\Capacitor\Capacitor_Walsin_MLCC.pdf
C77 C79 C88 C89 = CAPACITOR_NON-POL_0: ±5%,50V,NPO; Manufacturer: WALSIN; Part Number: 0402N330J500CT; Voltage: 50V; Datasheet: \\172.29.17.1\cn\WLAN\WLAN2\boarddesignLIB\136_component_database\Datasheet\Capacitor\Capacitor_Walsin_MLCC.pdf
C84 = CAP_NP_9
C91 C92 C108 C109 = CAPACITOR_NON-POL_0: ±20% X5R 25V; Manufacturer: WALSIN; Part Number: 0805X226M250CT; Voltage: 25V; Datasheet: \\172.29.17.1\cn\WLAN\WLAN2\boarddesignLIB\115_component_database\Datasheet\Capacitor\Capacitor_Walsin_MLCC.pdf
C94 = CAP_NP_14
C95 C121 = CAP_NP
C96 C105 = CAPACITOR_NON-POL_0: ±10%,25V,X7R; Manufacturer: WALSIN; Part Number: 0402B474K250CT; Voltage: 25V; Datasheet: \\172.29.17.1\cn\WLAN\WLAN2\boarddesignLIB\153_component_database\Datasheet\Capacitor\Capacitor_Walsin_MLCC.pdf
C97 = CAP_NP_4
C98 = CAP_NP_8
C99 = CAP_NP_2
C100 C101 = CAPACITOR_NON-POL_0: ±10%,25V,X5R; Manufacturer: WALSIN; Part Number: 0402X225K250CT; Voltage: 25V; Datasheet: \\172.29.17.1\cn\WLAN\WLAN2\boarddesignLIB\93_component_database\Datasheet\Capacitor\Capacitor_Walsin_MLCC.pdf
C102 = CAP_NP_19
C103 = CAP_NP_11
C104 = CAP_NP_16
C106 = CAP_NP_18
C107 = CAP_NP_6
C111 = CAP_NP_0
C112 C146 = CAP_NP_1
C113 = CAP_NP_17
C114 = CAP_NP_5
C115 = CAP_NP_7
C116 = CAP_NP_15
C117 = CAP_NP_10
C147 = CAP_NP_12
C148 = CAP_NP_3
C149 = CAP_NP_13
J3 J4 J17 = CON1
J5 = 2PIN_1.5mm
J6 = CON2_0
JP2 JP3 = 1X2PIN
L8 = INDUCTOR_3
R42 = R_11
R43 R44 R48 R49 = RES_0: +/-1%; Manufacturer: WALSIN; Part Number: WR04X22R0FTL; Datasheet: \\172.29.17.1\cn\WLAN\WLAN2\boarddesignLIB\01_component_database\Datasheet\Resistor\Resistor_Walsin_chipR.pdf
R47 = R_21
R17 R50 R55 = RES_0: JUMPER; Manufacturer: WALSIN; Part Number: WR08X000PTL; Datasheet: \\172.29.17.1\cn\WLAN\WLAN2\boarddesignLIB\01_component_database\Datasheet\Resistor\Resistor_Walsin_chipR.pdf
R51 = R_13
R52 = R_18
R53 = R_9
R54 = R_20
R56 = R_16
R58 = R_24
R59 = R_5
R60 = R_22
R61 = R_12
R62 = R_14
R63 = R_15
R65 = R_7
R66 = R_19
R67 = R_23
R68 = R_4
R69 = R_8
R70 = R_2
R71 = R
R72 = R_1
R75 = R_6
R167 = R_10
R168 = R_3
R169 = R_25
R170 = R_17
SD10-SD13 SD16 SD18-SD21 = Uni-directional_ESD_0: Uni-directional, 2V; Manufacturer: Amazing; Datasheet: \\172.29.17.1\cn\WLAN\WLAN2\boarddesignLIB\01_component_database\Datasheet\TVS\TVS_Amazing_AZ6118-01F-V1.0 1.pdf
SD1 SD7 SD14 SD15 = Bi-directional_ESD_0: Bi-directional, 8KV; Manufacturer: LittleFuse; Part Number: PGB1010603; Datasheet: \\172.29.17.1\cn\WLAN\WLAN2\boarddesignLIB\01_component_database\Datasheet\TVS\TVS_Littlefuse_101060.pdf
SD22 = Uni-directional_ESD_1: Uni-directional, 2V; Manufacturer: Amazing; Part Number: AZ6118-01F; Datasheet: \\172.29.17.1\cn\WLAN\WLAN2\boarddesignLIB\01_component_database\Datasheet\TVS\TVS_Amazing_AZ6118-01F-V1.0 1.pdf
SD23 = Uni-directional_ESD_2: Uni-directional, 2V; Datasheet: \\172.29.17.1\cn\WLAN\WLAN2\boarddesignLIB\01_component_database\Datasheet\TVS\TVS_Amazing_AZ6118-01F-V1.0 1.pdf
SD24 = Uni-directional_ESD_3: Uni-directional, 2V; Datasheet: \\172.29.17.1\cn\WLAN\WLAN2\boarddesignLIB\01_component_database\Datasheet\TVS\TVS_Amazing_AZ6118-01F-V1.0 1.pdf
SD25 = Uni-directional_ESD_0: Uni-directional, 2V; Datasheet: \\172.29.17.1\cn\WLAN\WLAN2\boarddesignLIB\01_component_database\Datasheet\TVS\TVS_Amazing_AZ6118-01F-V1.0 1.pdf
SD2-SD6 SD8 SD9 SD26-SD37 SD39 SD40 = Bi-directional_ESD_0: Bi-directional, 3.3V; Manufacturer: JDT Fuse; Part Number: JEN1006-3.3V-ULC; Datasheet: \\172.29.17.1\cn\WLAN\WLAN2\boarddesignLIB\01_component_database\Datasheet\TVS\TVS_JDTfuse_JEN1006-3.3V-ULC.pdf
TP1-TP5 = TEST_POINT
U8 U10 U12 U13 = SPH1642HT5H-1_3
U9 = 3S_DMIC_2
U11 = 3S_DMIC_3
U14 = AD52066_3
U15 = PJ313B
C122 = C_4
C123 = C_5
C124 = C_2
C125 = C
C126 = C_3
C127 = C_1
C130 = CAPACITOR_NON-POL_0: ±10%,50V,X5R; Manufacturer: WALSIN; Part Number: 0805X475K500CT; Voltage: 50V; Datasheet: \\172.29.17.1\cn\WLAN\WLAN2\boarddesignLIB\151_component_database\Datasheet\Capacitor\Capacitor_Walsin_MLCC.pdf
C131 = CAPACITOR_NON-POL_0: ±10%,50V,X7R; Manufacturer: WALSIN; Part Number: 0603B104K500CT; Voltage: 50V; Datasheet: \\172.29.17.1\cn\WLAN\WLAN2\boarddesignLIB\08_component_database\Datasheet\Capacitor\Capacitor_Walsin_MLCC.pdf
C132 C133 = CAPACITOR_NON-POL_0: ±5%,50V,NPO; Manufacturer: WALSIN; Part Number: 0402N100J500CT; Voltage: 50V; Datasheet: \\172.29.17.1\cn\WLAN\WLAN2\boarddesignLIB\52_component_database\Datasheet\Capacitor\Capacitor_Walsin_MLCC.pdf
C143 C154 = CAPACITOR_NON-POL_0: ±20%,6.3V,X5R; Manufacturer: WALSIN; Part Number: 0603X476M6R3CT; Voltage: 6.3V; Datasheet: \\172.29.17.1\cn\WLAN\WLAN2\boarddesignLIB\160_component_database\Datasheet\Capacitor\Capacitor_Walsin_MLCC.pdf
C152 = C_v2_3: X5R, ∮20%, 6.3V; Manufacturer: WALSIN; Part Number: 0805X106K6R3CT; Unit Price(USD): 0.01048
C155 = CAPACITOR_NON-POL_0: 10%,50V,X7R; Manufacturer: WALSIN; Part Number: 0402B102K500CT; Voltage: 50V; Datasheet: \\172.29.17.1\cn\WLAN\WLAN2\boarddesignLIB\74_component_database\Datasheet\Capacitor\Capacitor_Walsin_MLCC.pdf
C5 C156 C157 = CAPACITOR_NON-POL_0: ±10%,6.3V,X7R; Manufacturer: WALSIN; Part Number: 0402B105K6R3CT; Voltage: 6.3V; Datasheet: \\172.29.17.1\cn\WLAN\WLAN2\boarddesignLIB\83_component_database\Datasheet\Capacitor\Capacitor_Walsin_MLCC.pdf
C168 = C_v2_4: X5R, ∮20%, 6.3V; Manufacturer: WALSIN; Part Number: 0805X106K6R3CT; Unit Price(USD): 0.01048
C169 = C_v2_1: X5R, ∮20%, 6.3V; Manufacturer: WALSIN; Part Number: 0805X106K6R3CT; Unit Price(USD): 0.01048
C172 = C_v2_5: X5R, ∮20%, 6.3V; Manufacturer: WALSIN; Part Number: 0805X106K6R3CT; Unit Price(USD): 0.01048
C173 = C_v2_2: X5R, ∮20%, 6.3V; Manufacturer: WALSIN; Part Number: 0805X106K6R3CT; Unit Price(USD): 0.01048
J10 = CON6_2
J13-J16 = CON6_33
K1-K5 = BUTTON_0: Part Number: TAVPCM01-038ST-R
L12 = Inductor_Power: 3A,±20%; Manufacturer: Sunlord; Part Number: MWSA0402-4R7MT
P1 = PAD
Q1 = MOSFET_P: P沟道 20V 1.6A; Manufacturer: TECH PUBLIC; Part Number: FDN338P; Datasheet: \\172.29.17.1\cn\WLAN\WLAN2\boarddesignLIB\01_component_database\Datasheet\Triode-MOS Tube-Transistor\P-MOS_TECH PUBLIC_FDN338P_2021-09-03.pdf
R3 R166 = RES_0: JUMPER; Manufacturer: WALSIN; Part Number: WR06X000PTL; Datasheet: \\172.29.17.1\cn\WLAN\WLAN2\boarddesignLIB\01_component_database\Datasheet\Resistor\Resistor_Walsin_chipR.pdf
R76 R77 R79 R84 R88 R90 R91 = RES_0: +/-1%; Manufacturer: WALSIN; Part Number: WR02X27R0FAL; Datasheet: \\172.29.17.1\cn\WLAN\WLAN2\boarddesignLIB\01_component_database\Datasheet\Resistor\Resistor_Walsin_chipR.pdf
R78 R83 R87 = RES_0: +/-5%; Manufacturer: WALSIN; Part Number: WR04X471 JTL; Datasheet: \\172.29.17.1\cn\WLAN\WLAN2\boarddesignLIB\01_component_database\Datasheet\Resistor\Resistor_Walsin_chipR.pdf
R92 = R_v3_3
R20 R102 R173 R174 = RES_0: +/-1%; Manufacturer: WALSIN; Part Number: WR04X1001FTL; Datasheet: \\172.29.17.1\cn\WLAN\WLAN2\boarddesignLIB\01_component_database\Datasheet\Resistor\Resistor_Walsin_chipR.pdf
R103 = RES_0: +/-1%; Manufacturer: WALSIN; Part Number: WR04X10R0FTL; Datasheet: \\172.29.17.1\cn\WLAN\WLAN2\boarddesignLIB\01_component_database\Datasheet\Resistor\Resistor_Walsin_chipR.pdf
R18 R104 R114 R117 R121 R125 R127 = RES_0: +/-1%; Manufacturer: WALSIN; Part Number: WR04X4702FTL; Datasheet: \\172.29.17.1\cn\WLAN\WLAN2\boarddesignLIB\01_component_database\Datasheet\Resistor\Resistor_Walsin_chipR.pdf
R156 R158-R160 = RES_0: +/-1%; Manufacturer: WALSIN; Part Number: WR04X4701FTL; Datasheet: \\172.29.17.1\cn\WLAN\WLAN2\boarddesignLIB\01_component_database\Datasheet\Resistor\Resistor_Walsin_chipR.pdf
SD17 = DIODE_1: 肖特基二极管,30V 1A 440mV@1A; Manufacturer: Vishay; Part Number: MSS1P3L-M3/89A; Datasheet: \\172.29.17.1\cn\WLAN\WLAN2\boarddesignLIB\01_component_database\Datasheet\Diode\Diode_Vishay_MSS1P3L.pdf
U16 = CAT7103_2: ID: A
U17 = FPC-10P
U18 = FPC-24_4
U19 = CAT7103_1: ID: A
C6 = CAPACITOR_NON-POL_0: ±10%,10V,X7R; Manufacturer: MURATA; Part Number: GRM155Z71A225KE01D; Voltage: 10V
C13 = CAPACITOR_NON-POL_0: ±5%,50V,NPO; Manufacturer: WALSIN; Part Number: 0402N101J500CT; Voltage: 50V; Datasheet: \\172.29.17.1\cn\WLAN\WLAN2\boarddesignLIB\47_component_database\Datasheet\Capacitor\Capacitor_Walsin_MLCC.pdf
C118 C142 C150 C151 = CAPACITOR_NON-POL_0: ±5%,25V,NPO,Y; Manufacturer: WALSIN; Part Number: 0201N100J250CT; Voltage: 25V; Datasheet: \\172.29.17.1\cn\WLAN\WLAN2\boarddesignLIB\51_component_database\Datasheet\Capacitor\Capacitor_Walsin_MLCC.pdf
C134 C135 = CAPACITOR_NON-POL_0: ±10%,25V,X7R; Manufacturer: WALSIN; Part Number: 0402B103K250CT; Voltage: 25V; Datasheet: \\172.29.17.1\cn\WLAN\WLAN2\boarddesignLIB\50_component_database\Datasheet\Capacitor\Capacitor_Walsin_MLCC.pdf
C141 = CAP_NP_1: 10%,50V,X7R; Manufacturer: WALSIN; Part Number: 0402B102K500CT; Unit Price(USD): 0.00076; Voltage: 50V; Datasheet: \\172.29.17.1\cn\WLAN\WLAN2\boarddesignLIB\74_component_database\Datasheet\Capacitor\Capacitor_Walsin_MLCC.pdf
C144 = CAP_NP: 10%,50V,X7R; Manufacturer: WALSIN; Part Number: 0402B102K500CT; Unit Price(USD): 0.00076; Voltage: 50V; Datasheet: \\172.29.17.1\cn\WLAN\WLAN2\boarddesignLIB\74_component_database\Datasheet\Capacitor\Capacitor_Walsin_MLCC.pdf
C145 = CAPACITOR_NON-POL_0: ±10%,25V,X7R; Manufacturer: WALSIN; Part Number: 0603B105K250CT; Voltage: 25V; Datasheet: \\172.29.17.1\cn\WLAN\WLAN2\boarddesignLIB\85_component_database\Datasheet\Capacitor\Capacitor_Walsin_MLCC.pdf
CON1 = USB_TYPE_C: TYPE C 16 PIN TOP MOUNT SMT; Manufacturer: Molex; Part Number: 2171790001; Datasheet: \\172.29.17.1\cn\WLAN\WLAN2\boarddesignLIB\01_component_database\Datasheet\Connector\Type-C_Molex_2171790001_sd.pdf
CON2 = USB_CON_1X4P_ACON_3: CONTECK/22133-4W21-01; Class: IO; Colay_Alternate: N/A; Colay_Group: N/A; Component_Name: USB CON 1X4P,M,A TYPE,R/A,SMT; Critical_Part: N; Data_Sheet: K:\DataSheet\12-CONNECTOR\1213-003Q000.zip; Database_Update: 2009/2/7; Device: hh_usb_1x4p_4hd_m_ra_lf3; Electric_SPE: WHITE; FPLIST: hh_usb_1x4p_4hd_m_ra_lf3,usb_1x4p_4hd_m_ra_lf3; Green_HF: GA; HsFlag: A000000000; Manufacture: CONTECK; Modify_data: 2011/11/03; Optional: N/A; Package_Type: SMD; Part Number: 1213-003Q000; Part Type: 12CONNECTOR\USB; Sourcer: ¶À±Ò©ú(LA0803562); Subsystem_ID: N/A; Symbol_pic: K:\Symbol_Pic\12-CONNECTOR\1213-003Q000_MID.zip; metal_fabrication: 000000X100
D1 D2 = LED_0
D3 = LED_0: SMD 黄绿色  红色 压降2V，负载电流2mA
H1-H4 = HOLE_PTH: FOR PEGATRON ENTEK; Colay_Alternate: N/A; Colay_Group: N/A; Component_Name: TOOLING HOLE C205D126; Data_Sheet: K:\DataSheet\13-MECHANICAL\T-SH00002166.zip; Device: hole_c205d126; Modify_data: 2013/01/17; Optional: N/A; Package_Type: DIP; Part Number: T-SH00002166; Part Type: 13MECHANICAL\HOLE; Subsystem_ID: N/A
J1 J2 J11 = CON2
L1 = Inductor_Power: 3A,±20%; Manufacturer: Sunlord; Part Number: MWSA0402-1R5MT
R1 R171 = RES_0: +/-1%; Manufacturer: WALSIN; Part Number: WR04X5101FTL; Datasheet: \\172.29.17.1\cn\WLAN\WLAN2\boarddesignLIB\01_component_database\Datasheet\Resistor\Resistor_Walsin_chipR.pdf
R4 R5 = RES_0: +/-1%; Manufacturer: WALSIN; Part Number: WR04X2R49FTL; Datasheet: \\172.29.17.1\cn\WLAN\WLAN2\boarddesignLIB\01_component_database\Datasheet\Resistor\Resistor_Walsin_chipR.pdf
R9 = RES_0: +/-1%; Manufacturer: WALSIN; Part Number: WR04X3900FTL; Datasheet: \\172.29.17.1\cn\WLAN\WLAN2\boarddesignLIB\01_component_database\Datasheet\Resistor\Resistor_Walsin_chipR.pdf
R13 = RES_0: +/-1%; Manufacturer: WALSIN; Part Number: WR04X6801FTL; Datasheet: \\172.29.17.1\cn\WLAN\WLAN2\boarddesignLIB\01_component_database\Datasheet\Resistor\Resistor_Walsin_chipR.pdf
R14 = RES_0: +/-1%; Manufacturer: WALSIN; Part Number: WR04X2002FTL; Datasheet: \\172.29.17.1\cn\WLAN\WLAN2\boarddesignLIB\01_component_database\Datasheet\Resistor\Resistor_Walsin_chipR.pdf
R15 = RES_V: Manufacturer: WALSIN; Part Number: WR04X4700FTL; Unit Price(USD): 0.00032
R16 = RES_0: +/-1%; Manufacturer: WALSIN; Part Number: WR04X2201FTL; Datasheet: \\172.29.17.1\cn\WLAN\WLAN2\boarddesignLIB\01_component_database\Datasheet\Resistor\Resistor_Walsin_chipR.pdf
R19 = RES_0: +/-1%; Manufacturer: WALSIN; Part Number: WR04X1003FTL; Datasheet: \\172.29.17.1\cn\WLAN\WLAN2\boarddesignLIB\01_component_database\Datasheet\Resistor\Resistor_Walsin_chipR.pdf
R21 = RES_0: +/-1%; Manufacturer: WALSIN; Part Number: WR04X7502FTL; Datasheet: \\172.29.17.1\cn\WLAN\WLAN2\boarddesignLIB\01_component_database\Datasheet\Resistor\Resistor_Walsin_chipR.pdf
R22 = RES_0: +/-1%; Manufacturer: WALSIN; Part Number: WR04X2212FTL; Datasheet: \\172.29.17.1\cn\WLAN\WLAN2\boarddesignLIB\01_component_database\Datasheet\Resistor\Resistor_Walsin_chipR.pdf
R164 R165 = RES_0: +/-1%; Manufacturer: WALSIN; Part Number: WR04X1004FTL; Datasheet: \\172.29.17.1\cn\WLAN\WLAN2\boarddesignLIB\01_component_database\Datasheet\Resistor\Resistor_Walsin_chipR.pdf
R175 R176 = RES_0: +/-1%; Manufacturer: WALSIN; Part Number: WR04X1202FTL; Datasheet: \\172.29.17.1\cn\WLAN\WLAN2\boarddesignLIB\01_component_database\Datasheet\Resistor\Resistor_Walsin_chipR.pdf
U1 = USB2UART_0
U2 = RL5760_4
U3 = SY6281_0: Input voltage: 2.4V to 5.5V, 2A load current; Manufacturer: Silergy; Part Number: SY6281AAAC; Datasheet: \\172.29.17.1\cn\WLAN\WLAN2\boarddesignLIB\01_component_database\Datasheet\Power Supply Chip\Power Switch_Silergy_SY6281.pdf
U4 = SY8121C1ABC: 2A Load Current, 1.2MHz Switching Freq; Manufacturer: Silergy; Datasheet: \\172.29.17.1\cn\WLAN\WLAN2\boarddesignLIB\01_component_database\Datasheet\Power Supply Chip\DCDC_Silergy_AN_SY8121C1.pdf
U20 = LT1084-3_3.3

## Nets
AGND: C95.1 C113.2 C114.1 C115.1 C116.1 C117.1 JP2.2 JP3.2 R70.2 R71.2 R81.1 U15.2
GND: ANT1.2(G) ANT1.4(G) C1.2 C2.2 C3.1 C4.2 C5.1 C6.2 C7.2 C10.1 C11.2 C12.2 C14.2 C15.2 C16.2 C17.1 C18.1 C19.1 C20.1 C21.1 C22.1 C23.1 C24.1 C25.1 C26.1 C27.2 C28.1 C29.1 C30.1 C31.1 C32.2 C33.2 C34.2 C35.1 C36.1 C37.1 C38.2 C39.2 C40.2 C41.2 C42.2 C43.2 C44.2 C46.2 C47.2 C48.2 C49.1 C50.1 C51.1 C52.2 C53.1 C54.1 C55.1 C56.1 C57.1 C58.2 C59.1 C60.1 C61.1 C62.1 C63.1 C64.2 C65.1 C66.1 C67.1 C69.2 C70.2 C71.1 C72.1 C75.1 C76.1 C77.1 C79.1 C86.1 C88.1 C89.1 C91.2 C92.2 C93.2 C97.2 C98.1 C99.1 C100.1 C101.1 C103.1 C106.1 C108.2 C109.2 C110.2 C118.2 C119.2 C120.2 C121.1 C122.2 C123.2 C124.2 C125.2 C126.2 C127.2 C128.2 C129.2 C130.2 C131.1 C132.2 C133.2 C134.2 C135.2 C136.1 C137.1 C138.1 C139.1 C140.2 C141.2 C142.2 C143.2 C144.2 C145.1 C146.1 C147.1 C148.1 C149.1 C150.2 C151.2 C152.1 C153.1 C154.2 C156.2 C157.2 C168.1 C169.1 C172.1 C173.2 CON1.1(GND) CON1.8(GND) CON1.9(GND) CON1.16(GND) CON2.5(GND) IPEX1.2(G) IPEX1.3(G) IPEX2.2(G) IPEX2.3(G) J4.1 J5.3(GND1) J5.4(GND2) J10.6 J10.9 J10.14 J10.20 J10.25 J10.30 J10.34 J10.39 J13.7 J13.8 J14.5 J14.6 J15.1 J15.5 J15.6 J16.5 J17.1 K1.3 K1.4 L15.1 L16.1 L17.2 P1.6(VSSQ/VSS) P1.10(VSS) P1.12(GND1) P1.13(GND2) P1.14(GND3) P1.15(GND4) R1.2 R13.2 R14.1 R16.2 R20.2 R21.2 R22.2 R27.1 R28.1 R31.2 R34.1 R35.1 R51.1 R56.2 R61.2 R65.1 R66.1 R67.1 R74.1 R81.2 R82.1 R103.2 R105.2 R111.2 R164.1 R165.1 R167.2 R168.2 R169.2 R170.2 R171.2 SD1.2 SD2.2 SD3.2 SD4.2 SD5.2 SD6.2 SD7.2 SD8.2 SD9.2 SD10.2 SD11.2 SD12.2 SD13.2 SD14.2 SD15.2 SD16.2 SD18.2 SD19.2 SD20.2 SD21.2 SD22.2 SD23.2 SD24.2 SD25.2 SD26.2 SD27.2 SD28.2 SD29.2 SD30.2 SD31.2 SD32.2 SD33.2 SD34.2 SD35.2 SD36.2 SD37.2 SD39.2 SD40.2 TP1.1 TP2.1 TP3.1 TP4.1 U1.1(GND) U1.5(GND) U2.25(GND) U3.2(GND) U4.2(GND) U5.2(NC) U5.4(GND_DCDC_CORE) U5.45(GND) U5.63(GND_AUD) U5.93(GND) U5.112(GND_DCDC_MEM) U5.141(GND_DCDC_AUD) U5.145(EPAD_GND) U6.4(GND) U7.2(GND) U7.4(GND) U7.6(GND) U8.1(GND) U8.2(GND) U8.3(GND) U8.5(GND) U9.5(GND) U9.6(GND) U9.7(GND) U9.8(GND) U10.1(GND) U10.2(GND) U10.3(GND) U10.5(GND) U11.2(L/R) U11.5(GND) U11.6(GND) U11.7(GND) U11.8(GND) U12.1(GND) U12.2(GND) U12.3(GND) U12.5(GND) U13.1(GND) U13.2(GND) U13.3(GND) U13.5(GND) U14.3(LINP) U14.4(LINN) U14.8(AGND) U14.19(PGND2) U14.24(PGND1) U14.29(GND) U17.1 U17.11(GND) U17.12(GND) U18.3(GND) U18.6(GND) U18.9(GND) U18.12(GND) U18.15(GND) U18.21(GND) U18.23(GND) U18.49(GND) U18.50(GND) U19.2(GND) U21.1(S-PAD) U21.2(S-PAD) U21.3(S-PAD) U21.4(S-PAD) U21.5(S-PAD) U21.6(S-PAD) U21.7(S-PAD) U21.8(S-PAD) U22.4(GND) U22.9(EPAD) X1.2(GND) X1.4(GND)
PVCC: C91.1 C92.1 C93.1 C108.1 C109.1 C110.1 R50.2 R55.2 R59.2 TP5.1 U14.15(PVCCR2) U14.16(PVCCR1) U14.27(PVCCL2) U14.28(PVCCL1)
V33SD_IN: C119.1 C120.1 P1.4(VCCQ/VDD) P1.11(VCC) R99.1 R104.2 R114.2 R117.2 R121.2 R125.2 R127.2 SD33.1
VBAT_MEAS: J15.10 U5.17(BAT_MEAS)
VBUS: C1.1 C4.1 CON2.1(VBUS) R9.2 R10.2 R166.2 SD7.1 U3.1(OUT)
VBUS_OTG: R9.1 U5.118(VBUS_OTG)
VCCIO: C5.2 R2.1 R6.2 R15.1 R173.2 R174.2 U2.24(VDD_IO)
VDD5: C3.2 C6.1 C11.1 C12.1 CON1.2(VBUS) CON1.7(VBUS) CON1.10(VBUS) CON1.15(VBUS) J10.2 J10.4 R18.1 R55.1 R166.1 R182.2 SD1.1 U1.2(5V_OUT) U1.3(5V_OUT) U1.4(5V_IN) U2.14(VIN) U3.5(IN) U4.5(IN)
VDD09: C17.2 C18.2 C20.2 C24.2 C37.2 C38.1 C42.1 C52.1 C137.2 C138.2 L2.1 U5.18(VDL_CORE) U5.77(VDL_CORE) U5.88(VDL_MEM) U5.91(VDL_CORE) U5.117(VAL_USB) U5.125(VAL_MIPI) U5.128(VDL_CORE) U5.140(VDL_CORE)
VDD18_A: C27.1 C28.2 C55.2 L3.1 R23.2 U5.74(VAM_AUD)
VDD18_D: C29.2 C30.2 C44.1 C46.1 C47.1 C48.1 L4.1 R29.2 U5.87(VDM_MEM) U5.90(VDM_MEM) U5.95(VDM_MEM)
VDD18_R: C49.2 C50.2 C54.2 C61.2 R23.1 U5.28(VAM_AFE) U5.31(VRM_SYN) U5.35(VRM_RF) U5.50(VRM_FE_BT)
VDD33: C13.1 C14.1 C15.1 C143.1 C154.1 D3.1(ANODE) J10.1 J10.17 J11.1 K3.1 K3.2 K4.1 K4.2 K5.1 K5.2 L1.2 Q1.2(SOURCE) R3.1 R6.1 R17.1 R19.1 R25.2 R26.2 R42.2 R47.2 R54.2 R68.1 R99.2 R101.1 R156.2 R158.2 R159.2 R160.1 U16.2(VDD)
VDD33_LCD: C128.1 C129.1 C155.1 L12.1 Q1.3(DRAIN) R3.2 R142.1 U18.1(VDDIO_3V3) U18.2(VDD_3V3) U19.6(VIN)
VDD33_S: C19.2 C21.2 C22.2 C23.2 C25.2 C26.2 C31.2 C32.1 C33.1 C34.1 C35.2 C36.2 C40.1 C41.1 C53.2 C56.2 C57.2 C58.1 C59.2 C60.2 C62.2 C136.2 J11.2 R17.2 R24.2 R30.1 R32.2 R33.1 R163.2 R177.2 R181.2 U5.1(NC) U5.3(VAH_DCDC_CORE) U5.11(VDH_IO0) U5.16(VAH_PLL) U5.23(VDH_IO1) U5.33(VRH_SYN) U5.34(NC) U5.37(NC) U5.39(VRH_PAD_A) U5.40(VRH_PA_A) U5.47(VRH_PA_G) U5.48(VRH_PAD_G) U5.49(VRH_FE_BT) U5.52(VRH_PA_BT) U5.99(VDH_IO3) U5.105(VDH_IO4) U5.114(VAH_DCDC_MEM) U5.115(VAH_USB) U5.129(VDH_IO5) U5.134(VDH_IO6__|__________NC) U5.137(NC__|__VDH_IO6) U5.143(VAH_DCDC_AUD) U6.8(VCC) U22.8(VCC)
1SD_CD: C16.1 P1.9(CD) R91.1 R104.1 SD37.1
1SD_CLK: C125.1 P1.5(CLK) R84.1 SD34.1
1SD_CMD: C124.1 P1.3(CMD) R79.1 R114.1 SD32.1
1SD_D0: C127.1 P1.7(D0) R88.1 R117.1 SD35.1
1SD_D1: C126.1 P1.8(D1) R90.1 R121.1 SD36.1
1SD_D2: C122.1 P1.1(D2) R76.1 R125.1 SD40.1
1SD_D3: C123.1 P1.2(D3) R77.1 R127.1 SD39.1
AKEY: C121.2 R74.2 R80.1 R92.2 R93.2 R94.2 SD16.1
AOUT_LP: C107.1 J6.1 R67.2
AOUT_LPE: C112.1 J6.3
BLEN: C157.1 R105.1 R128.2 R142.2 U19.4(EN)
BT_ANT: ANT1.1(BT) C67.2 L5.2
BT_ANT0: C66.2 L5.1 R38.1
CC1: CON1.3(CC1) R171.1
CC2: CON1.11(CC2) R1.1
CHIP_EN: C10.2 C145.2 K1.1 K1.2 R7.2 R24.1 SD8.1 U5.106(CHIP_EN)
DTR_N: R176.2 U2.22(DTR_N) U20.1(E0)
FT232_DN: C142.1 CON1.5(DN1) CON1.13(DN2) SD3.1 U2.11(DM)
FT232_DP: C118.1 CON1.4(DP1) CON1.12(DP2) SD2.1 U2.10(DP)
FT_LOG_RX: J2.1 R12.2 U1.7(FT232_RX) U2.1(RXD)
FT_LOG_TX: J1.1 R11.2 U1.6(FT232_TX) U2.21(TXD)
GTOUCH: R152.1 U17.3
HP_DET: R73.1 R179.2
HSDM: R5.2 U5.120(HSDM)
HSDM_USB: C151.1 CON2.2(D-) R5.1 SD6.1
HSDP: R4.2 U5.119(HSDP)
HSDP_USB: C150.1 CON2.3(D+) R4.1 SD5.1
ID_USB: R109.2 R184.1 U5.116(ID)
LCD_CTP_INT: R155.2 U18.17(I2C_INT)
LCD_CTP_RST: R153.2 U18.16(I2C_RST)
LCD_CTP_SCL: R131.2 U18.5(I2C_SCL)
LCD_CTP_SDA: R133.2 U18.4(I2C_SDA)
LCD_Power_EN#: R102.1 R106.2
LCD_PWM: R157.2 U18.19(LCD_PWM)
LCD_RESET: R111.1 R149.2 U18.18(LCD_RESET)
LCD_TE: R146.2 U18.20(LCD_TE)
LEDA: C130.1 C131.2 SD17.1 U18.24(BLA) U19.5(OV)
LEDB: R87.1 U16.4(Blue)
LEDG: R83.1 U16.3(Green)
LEDK: R103.1 U18.22(BLK) U19.3(FB)
LEDR: R78.1 U16.1(Red)
LX_AUD: L3.2 U5.142(LX_AUD)
LX_DCORE: L2.2 U5.5(LX_CORE)
LX_MEM: L4.2 U5.113(LX_MEM)
MIC1_N: C74.2 R167.1
MIC1_P: C73.2 C77.2 SD10.1 U8.4(OUT)
MIC2_N: C80.2 R169.1
MIC2_P: C78.2 C88.2 SD12.1 U12.4(OUT)
MIC3_N: C82.2 R168.1
MIC3_P: C79.2 C81.2 SD11.1 U10.4(OUT)
MIC4_N: C85.2 R170.1
MIC4_P: C83.2 C89.2 SD13.1 U13.4(OUT)
MIC5_N: C90.2 C94.2 R64.1
MIC5_P: C84.2 C87.2 R57.1
MIPITX_CKN: U5.123(DSI_CN) U18.11(DSI_CN)
MIPITX_CKP: U5.124(DSI_CP) U18.10(DSI_CP)
MIPITX_DATAN_0: U5.126(DSI_DN0) U18.8(DSI_DN0)
MIPITX_DATAN_1: U5.121(DSI_DN1) U18.14(DSI_DN1)
MIPITX_DATAP_0: U5.127(DSI_DP0) U18.7(DSI_DP0)
MIPITX_DATAP_1: U5.122(DSI_DP1) U18.13(DSI_DP1)
PA0: R132.2 R135.2 U5.7(PA0)
PA1: R137.2 R139.2 U5.6(PA1)
PA2: R141.2 R144.2 U5.8(PA2)
PA3: R148.2 R151.2 U5.9(PA3)
PA4: R130.2 R134.2 U5.10(PA4)
PA5: R136.2 R138.2 U5.15(PA5)
PA6: R140.2 R143.2 U5.13(PA6)
PA7: R145.2 R150.2 U5.12(PA7)
PA8: R152.2 R154.2 U5.14(PA8)
PA9: J10.26 R155.1 U5.19(PA9)
PA10: J10.15 R78.2 R153.1 U5.20(PA10)
PA11: J10.32 U5.21(PA11)
PA12: J10.33 U5.22(PA12)
PA13: C152.2 J10.19 R83.2 R157.1 U5.24(PA13)
PA14: C153.2 J10.21 R87.2 R149.1 U5.25(PA14)
PA15: J10.23 R146.1 R179.1 U5.26(PA15)
PA16: J10.24 R106.1 R128.1 U5.27(PA16)
PA20: C73.1 J13.1 U5.61(MICIN1P)
PA21: C74.1 J13.2 U5.62(MICIN1N)
PA22: C78.1 J13.3 U5.59(MICIN2P)
PA23: C80.1 J13.4 U5.60(MICIN2N)
PA24: C81.1 J13.5 U5.57(MICIN3P)
PA25: C82.1 J13.6 U5.58(MICIN3N)
PA26: C83.1 J13.9 U5.55(MICIN4P)
PA27: C85.1 J13.10 U5.56(MICIN4N)
PA28: C87.1 J14.1 U5.53(MICIN5P)
PA29: C90.1 J14.2 U5.54(MICIN5N)
PA30: J14.3 R40.1 U5.67(MICBIAS1)
PA31: J14.4 R45.1 R72.2 U5.69(MICBIAS2)
PA_0: J10.16 R135.1
PA_1: J10.18 R139.1
PA_2: J10.7 R80.2 R144.1
PA_3: J10.11 R151.1
PA_4: J10.12 R134.1
PA_5: J10.13 R138.1
PA_6: J10.22 R143.1
PA_7: J10.29 R150.1
PA_8: J10.31 R154.1
PA_SD_B: R52.2 R97.1
PB0: J14.7 R41.1 U5.66(MICBIAS3)
PB1: J14.8 R46.1 U5.68(MICBIAS4)
PB3: J6.2 J14.9 U5.71(LINEOUTLP)
PB4: J14.10 R63.2 U5.70(LINEOUTLN)
PB5: C111.1 J16.1 U5.75(LINEOUTRP)
PB6: J16.2 U5.76(LINEOUTRN)
PB7: J10.35 U5.78(PB7)
PB8: J10.36 U5.79(PB8)
PB9: J10.37 U5.80(PB9)
PB10: C168.2 J10.3 R133.1 R156.1 U5.81(PB10)
PB11: C169.2 J10.5 R131.1 R158.1 U5.82(PB11)
PB12: J10.38 U5.83(PB12)
PB13: J10.40 U5.84(PB13)
PB14: J16.3 U5.94(PB14)
PB15: J16.4 U5.96(PB15)
PB16: J16.6 U5.97(PB16)
PB17: J16.7 R183.1 U5.98(PB17)
PB17/ID_USB: R10.1 R14.2 R182.1 R183.2 R184.2 U3.4(ENB)
PB18: J16.8 U5.100(PB18)
PB19: R97.2 R100.2 U5.101(PB19)
PB20: J10.8 U5.102(PB20)
PB21: J16.9 R25.1 R27.2 R44.2 R49.2 U5.103(PB21)
PB22: J16.10 R26.1 R28.2 R43.2 R48.2 U5.104(PB22/TM_DIS)
PB23: C132.1 J1.2 R11.1 U5.111(PB23)
PB24: C133.1 J2.2 K2.1 K2.2 R8.1 R12.1 R163.1 SD9.1 U5.107(PB24/UD_DIS)
PB25: R76.2 R85.2 U5.138(PB25)
PB26: R77.2 R95.2 U5.139(PB26)
PB27/PC1: R79.2 R107.2 R112.2 U5.130(PB27__|_________PC1)
PB28/PC2: R84.2 R119.2 R126.2 U5.131(PB28__|_________PC2)
PB29/PC3: R86.2 R88.2 R89.2 U5.132(PB29__|_________PC3)
PB30/PC4: R90.2 R96.2 R98.2 U5.133(PB30__|_________PC4)
PB31/PC5: R108.2 R110.2 U5.135(PB31__|_________PC5)
PB_19: J10.10 R100.1
PB_25: C172.2 J10.27 R85.1 R159.1
PB_26: C173.1 J10.28 R95.1 R160.2
PB_27: J15.3 R107.1
PB_28: J15.2 R119.1
PB_29: J15.7 R86.1
PB_30: J15.4 R96.1
PB_31: J15.9 R108.1
PC0/PC6: R91.2 R120.2 R124.2 U5.136(PC0__|_________PC6)
PC_0: J15.8 R120.1
RFIO_A: C8.1 L13.2 U5.41(RFIO_A)
RFIO_BT: C68.1 L6.1 U5.51(RFIO_BT)
RFIO_G: C76.2 L14.2 U5.46(RFIO_G)
RTS_N: R175.1 U2.23(RTS_N) U20.4(E1)
SPI_CLK: R126.1 U6.6(SCLK) U22.6(SCLK)
SPI_CS: R30.2 R124.1 U6.1(CS) U22.1(\\~{C}S)
SPI_DATA0: R89.1 U6.5(SIO0) U22.5(SI/IO0)
SPI_DATA1: R110.1 U6.2(SIO1) U22.2(SO/IO1)
SPI_DATA2: R33.2 R98.1 U6.3(WP/SIO2) U22.3(\\~{W}P/IO2)
SPI_DATA3: R32.1 R112.1 U6.7(Hold/SIO3) U22.7(\\~{HOL}D/IO3)
SPK_N: C101.2 J5.1(S1) L8.1 R62.1 SD15.1
SPK_P: C100.2 J5.2(S2) L9.1 R58.1 SD14.1
TOUCH0_ADC0: R132.1 U17.9
TOUCH1_ADC1: R137.1 U17.10
TOUCH2_ADC2: R141.1 U17.8
TOUCH3_ADC3: R148.1 U17.7
TOUCH4_ADC4: R130.1 U17.6
TOUCH5_ADC5: R136.1 U17.2
TOUCH6: R140.1 U17.4
TOUCH7: R145.1 U17.5
VREF_DRAM: C39.1 R29.1 R31.1 U5.92(MREF)
WLAN_ANT: ANT1.3(WLAN) C72.2 L7.2
WLAN_ANT1: C71.2 L7.1 R39.2
XI: U5.29(XI) X1.1(XTALP)
XO: U5.30(XO) X1.3(XTALP)
N18158134: C174.1 R35.2 U5.86(RREF)
N19107289: C69.1 C139.2 C140.1 L6.2 R36.2 R38.2
N19107386: IPEX1.1(Feed) R36.1
N19108975: C65.2 C70.1 R37.1 R39.1 U7.5(RFIO)
N19108979: IPEX2.1(Feed) R37.2
N19108983: C2.1 L13.1 U7.3(5G)
N19108997: C45.2 L14.1 U7.1(2G)
N19122278: L12.2 SD17.2 U19.1(SW)
N19158883: C63.2 U5.64(AUD_VREF)
N19158983: C64.1 U5.65(LDOA_OUT)
N19169394: C149.2 R41.2 SD21.1 U10.6(VDD)
N19169778: C75.2 R42.1 SD26.1 U9.1(VDD) U9.2(L/R)
N19169809: C86.2 R47.1 SD29.1 U11.1(VDD)
N19169881: C146.2 R40.2 SD18.1 U8.6(VDD)
N19169891: C147.2 R45.2 SD19.1 U12.6(VDD)
N19169978: R49.1 SD31.1 U11.4(DATA)
N19171692: C97.1 C102.2 R56.1 R57.2 R58.2
N19171694: C102.1 C106.2 R62.2 R64.2 R65.2
N19172475: C148.2 R46.2 SD20.1 U13.6(VDD)
N19173360: C104.1 R63.1 R66.2
N19173627: C105.2 U14.17(BSPR) U14.21(BSNR)
N19173629: C105.1 L9.2 U14.18(OUTPR) U14.20(OUTNR)
N19173633: C99.2 R60.1 U14.9(GVDD)
N19173635: C107.2 U14.12(RINP)
N19173637: C98.2 R59.1 U14.7(AVCC)
N19173650: R51.2 R52.1 R53.2 U14.1(~{SD})
N19173684: R53.1 R54.1 U14.2(~{FAULT})
N19173712: C103.2 R60.2 R61.1 U14.10(PLIM)
N19173726: C104.2 U14.11(RINN)
N19173773: C96.2 U14.22(BSNL) U14.26(BSPL)
N19173777: C96.1 L8.2 U14.23(OUTNL) U14.25(OUTPL)
N19197274: C135.1 CON1.17(PAD) CON1.18(PAD) CON1.19(PAD) CON1.20(PAD) R165.2
N19197406: R2.2 U1.8(VCC_IO)
N19198736: CON2.4(ID) R109.1 SD4.1
N19199670: D3.2(CATHODE) R16.1
N19221748: J3.1 R50.1
N19230922: K2.3 K2.4 R20.1
N19290584: R43.1 SD27.1 U9.3(CLK)
N19290655: R48.1 SD30.1 U11.3(CLK)
N19291102: JP3.1 L11.2 R70.1 SD23.1 U15.4
N19291117: JP2.1 L10.2 R71.1 SD24.1 U15.3
N19291174: C84.1 C95.2 C117.2 R72.1 R75.2
N19291176: C111.2 C114.2 L10.1
N19291188: C94.1 C113.1 R75.1 SD22.1 U15.1
N19291208: C112.2 C115.2 L11.1
N19291218: C116.2 R69.1 R73.2
N19291222: R68.2 R69.2 SD25.1 U15.6
N19309684: R34.2 U5.89(NC__|__ZQ)
N19317782: C13.2 R19.2 R22.1 U4.3(FB)
N19317823: R18.2 R21.1 U4.4(EN)
N19317917: C9.2 L1.1 U4.6(LX)
N19317969: C9.1 U4.1(BS)
N19350952: R13.1 U3.3(ISET)
N19357698: C134.1 CON2.6(GND) CON2.7(GND) CON2.8(GND) CON2.9(GND) R164.2
N19544045: C141.1 R15.2 U2.13(RESET_N)
N19544063: D2.1(ANODE) R173.1
N19544079: D2.2(CATHODE) U2.16(GPB1)
N19544115: D1.2(CATHODE) U2.15(GPB0)
N19544121: D1.1(ANODE) R174.1
N19544190: C7.1 C144.1 U2.12(VO_33)
N19544535: R176.1 U20.5(B1)
N19544537: R175.2 U20.2(B0)
N19558959: C43.1 R177.1 U5.85(VDH_IO2)
N19617861: C51.2 R181.1 U5.32(VAH_XTAL)
N19691519: R44.1 SD28.1 U9.4(DATA)
N19758757: R7.1 U20.3(C1)
N19758908: R8.2 U20.6(C0)
N19817029: C45.1 L16.2
N19817634: C8.2 L17.1
N19833118: C174.2 R82.2
N19948615: K3.3 K3.4 R93.1
N19948618: K4.3 K4.4 R94.1
N19948621: K5.3 K5.4 R92.1
N20138888: C155.2 C156.1 Q1.1(GATE) R101.2 R102.2
N20183218: C68.2 L15.2

Not connected (* = marked no-connect by the designer): CON1 6(SBU1)* 14(SBU2)*; H1 1*; H2 1*; H3 1*; H4 1*; U2 2(RI_N)* 3(TXEN)* 4(DSR_N)* 5(DCD_N)* 6(CTS_N)* 7(SUSP_N)* 8(GPB3)* 9(GPB2)* 17(GPB4)* 18(GPB5)* 19(XI)* 20(XO)*; U5 36(NC)* 38(NC)* 42(NC)* 43(RFIN_A)* 44(RFIN_G)* 72(NC)* 73(NC)* 108(NC)* 109(NC)* 110(NC)* 144(NC)*; U14 5(NC1)* 6(NC2)* 13(NC3)* 14(NC4)*; U15 5*; U18 25(NC)* 26(NC)* 27(NC)* 28(NC)* 29(NC)* 30(NC)* 31(NC)* 32(NC)* 33(NC)* 34(NC)* 35(NC)* 36(NC)* 37(NC)* 38(NC)* 39(NC)* 40(NC)* 41(NC)* 42(NC)* 43(NC)* 44(NC)* 45(NC)* 46(NC)* 47(NC)* 48(NC)*

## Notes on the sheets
sheet 1
- USB&POWER
- USB OTG
- USB TypeC  (Power and FT232)
- 90ohm
- PL2303GC QFN24 4X4
  USB TO UART
- R166 reserve for force host mode
- Auto-Download Circuit
- Colay : USB to UART circuit & USB2UART Module
- 5V --> +3.3V SWR
- CHIP_EN
- CHIP ENABLE CONTROL
- POWER LED
- Func.
- SW CTRL
- Press
- pull low
- Release
- default setting
- UART_DOWNLOAD
sheet 2
- RTL8730EL_QFN144
- VDD18_SPS1：
- VDD18_SPS2：
- RTL8730ELM
- FLASH
- RTL8730ELH
- Close to
  pin92
- Importance!
- 1, External flash is only needed for RTL8730ELM, not for RTL8730ELH.
  It's necessary to configure the correct pull-up or pull-down
  resistor for PB21 according to the external flash type, which means:
- RTL8730ELH-VA3&VA7
- RTL8730ELH-VA8&RTL8730ELM
- High for NOR  flash and Low for NAND flash.
- NOR FLASH
- PU
- R25 Mounted
- NAND FLASH
- PD
- R27 Mounted
- 2, U6 & U22 here is just for different footprints. Actually only one
  of them is needed when placed.
- Xtal function
- When dedicated BT is not used
  PIn51&Pin52can be NC
- R181 here is to prevent noise of the VDD33_S
  power from affecting audio performance
- WLAN_RF
- BT_RF
- Antenna
- When dedicated BT is not used
  BT_RF part can be NC
- Colay
- Colay
- C139/C140 ESD
  optional but
  recommended
- C65/C70 ESD
  optional but
  recommended
- For BT & WLAN coexistence, L15 is added additionally,
  meanwhile the value of C68 should be changed to 0.8nH & L15 to be 1pF
- For BT & WLAN coexistence：
  L16 & L17  are added additionally.
  If pcb placement space is enough, L16 will be better to placed at the middle of C76 and ground.
  Meanwhile, the recommended value of C76 is 0.6nH, L16 1pF, C8 2.4nH & L17 changed to 1.8pF.
sheet 3
- AUDIO
- DMIC
- AMIC
- Note: MIC cap above should close to 8730E
- Left : DMIC1   L/R=HIGH，CLK=HIGH,DATA=VALID
  Rignt: DMIC2   L/R=LOW，CLK=LOW,DATA=VALID
- Co-lay
- SPEAKER
- AEC
- Colay
- Earphone Jack (CTIA)
- L
- R
- GND
- MIC
sheet 4
- Peripheral
- SD Card/EMMC
- USER LED
- USER KEY
- AKEY max = 1.8V
- R_up / Kohm   Vadc / V
      47         0.5789
      34         0.75
      24.9       0.9456
      19.728     1.11
      16.277     1.2599
      14.374     1.3539
      11.007     1.5709
- When RTL8730ELM is mounted, 0 ohm jumping resistors of GPIO nets
  connected with flash such as PB27, PB28, PB29, PB30, PB31, PC0 can be
  removed. It means these GPIOs can be directly connnected to corresponding
  Flash nets
- MIPI DSI
- 4 inch TFT LCD
- CAP TOUCH
- Realtek 7inch LCD:
  R103=2.2Ω
  Realtek 3.97inch LCD:
  R103=10Ω
- GPIOs
- Reserve for internal test
